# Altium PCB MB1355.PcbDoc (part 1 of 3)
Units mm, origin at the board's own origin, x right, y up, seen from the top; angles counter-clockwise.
Board outline 70.13 x 64.58 mm, 4 copper layers (L1, L2, L3, L4), stack 1.565 mm thick; 206 components, 160 nets, 707 pads, 1364 vias.
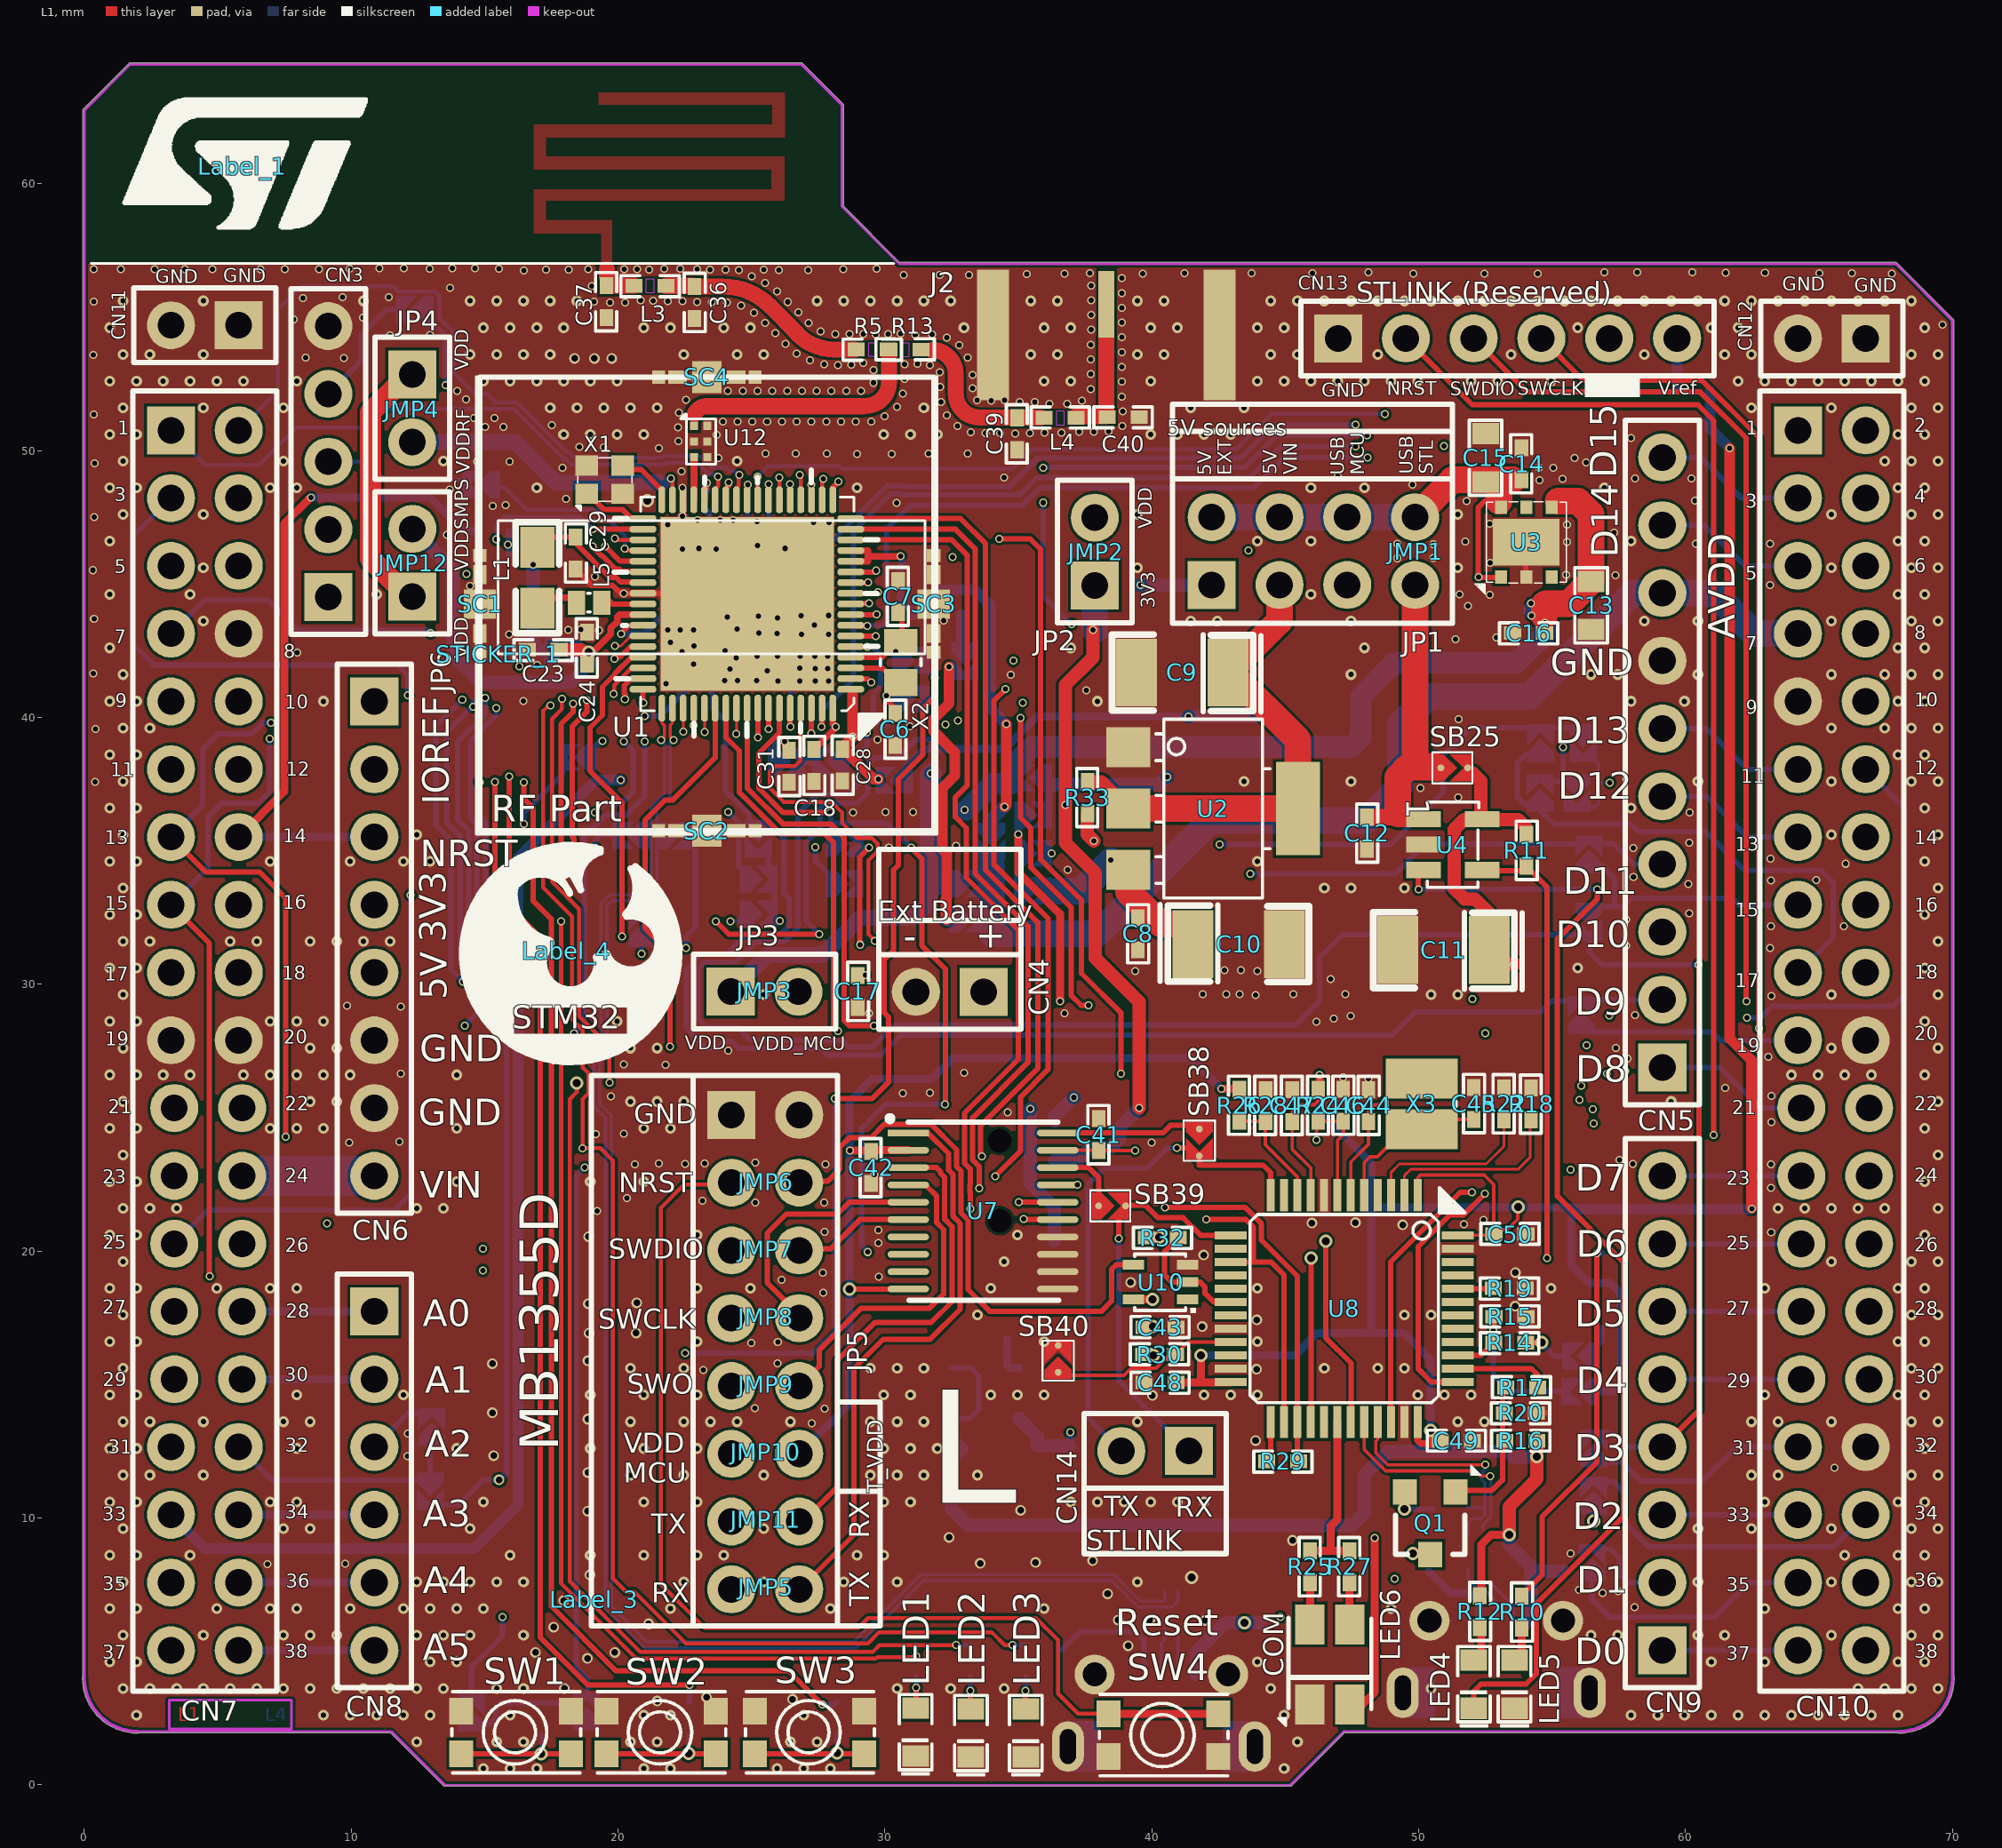
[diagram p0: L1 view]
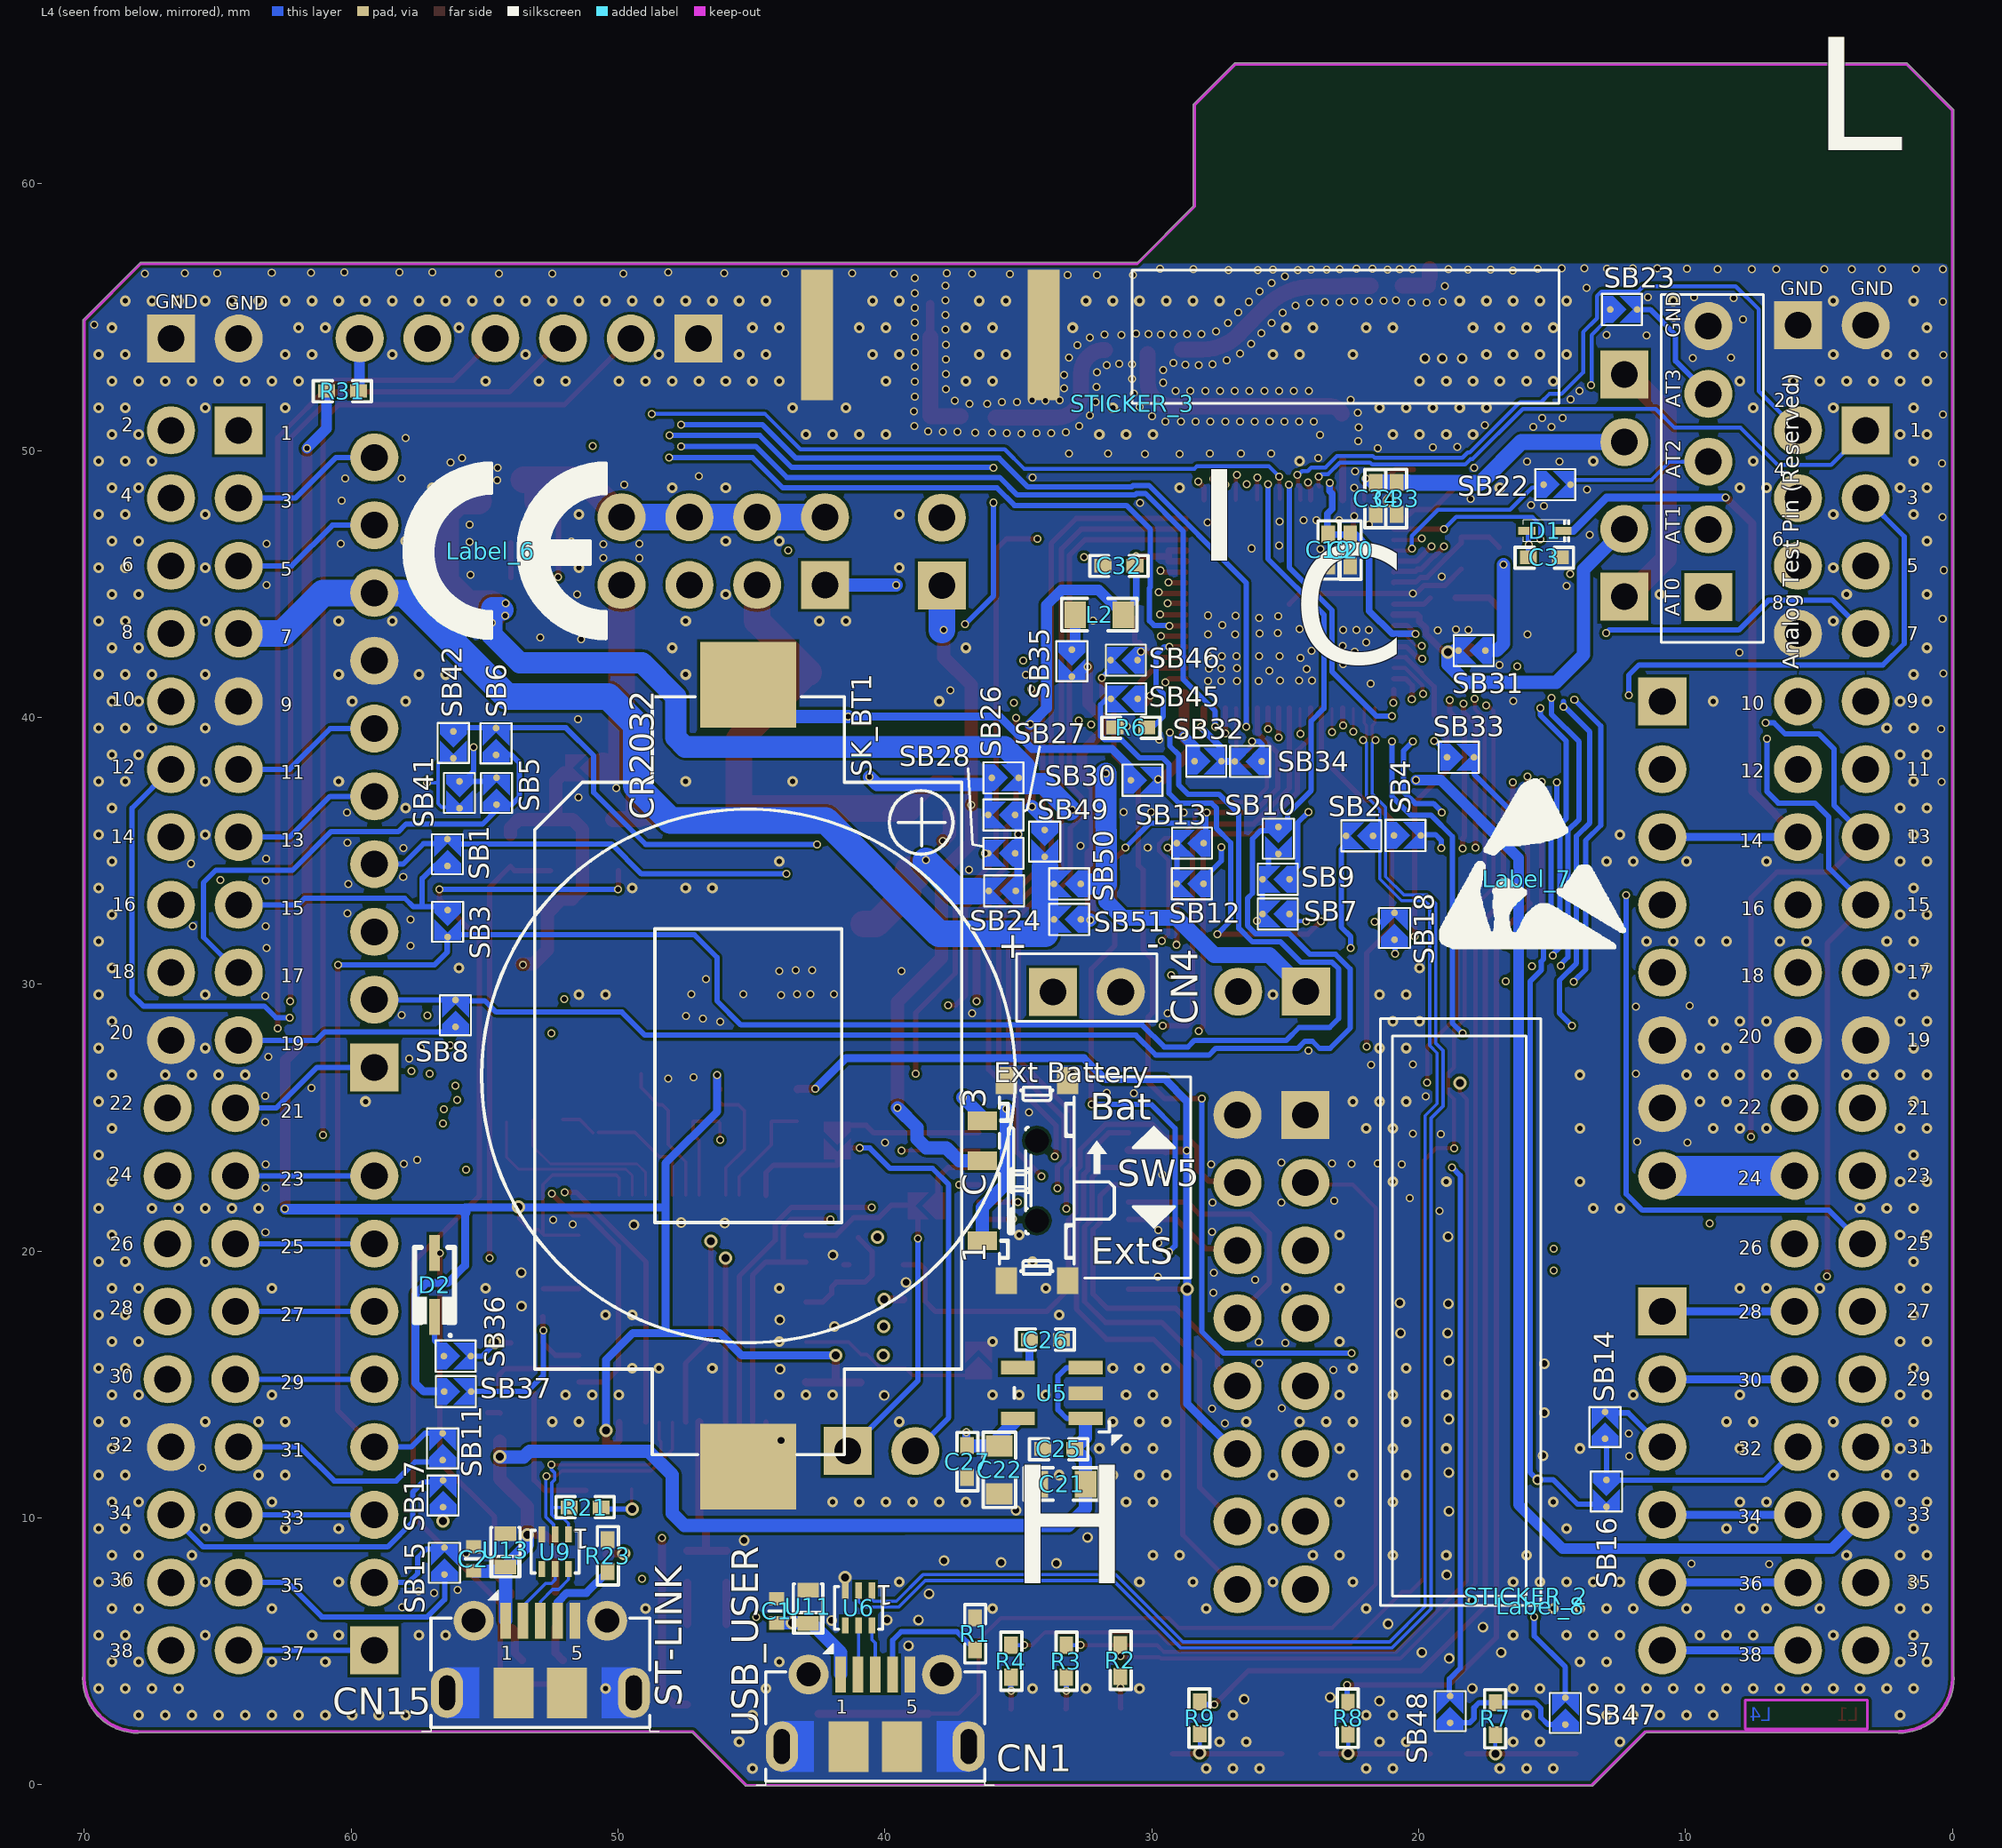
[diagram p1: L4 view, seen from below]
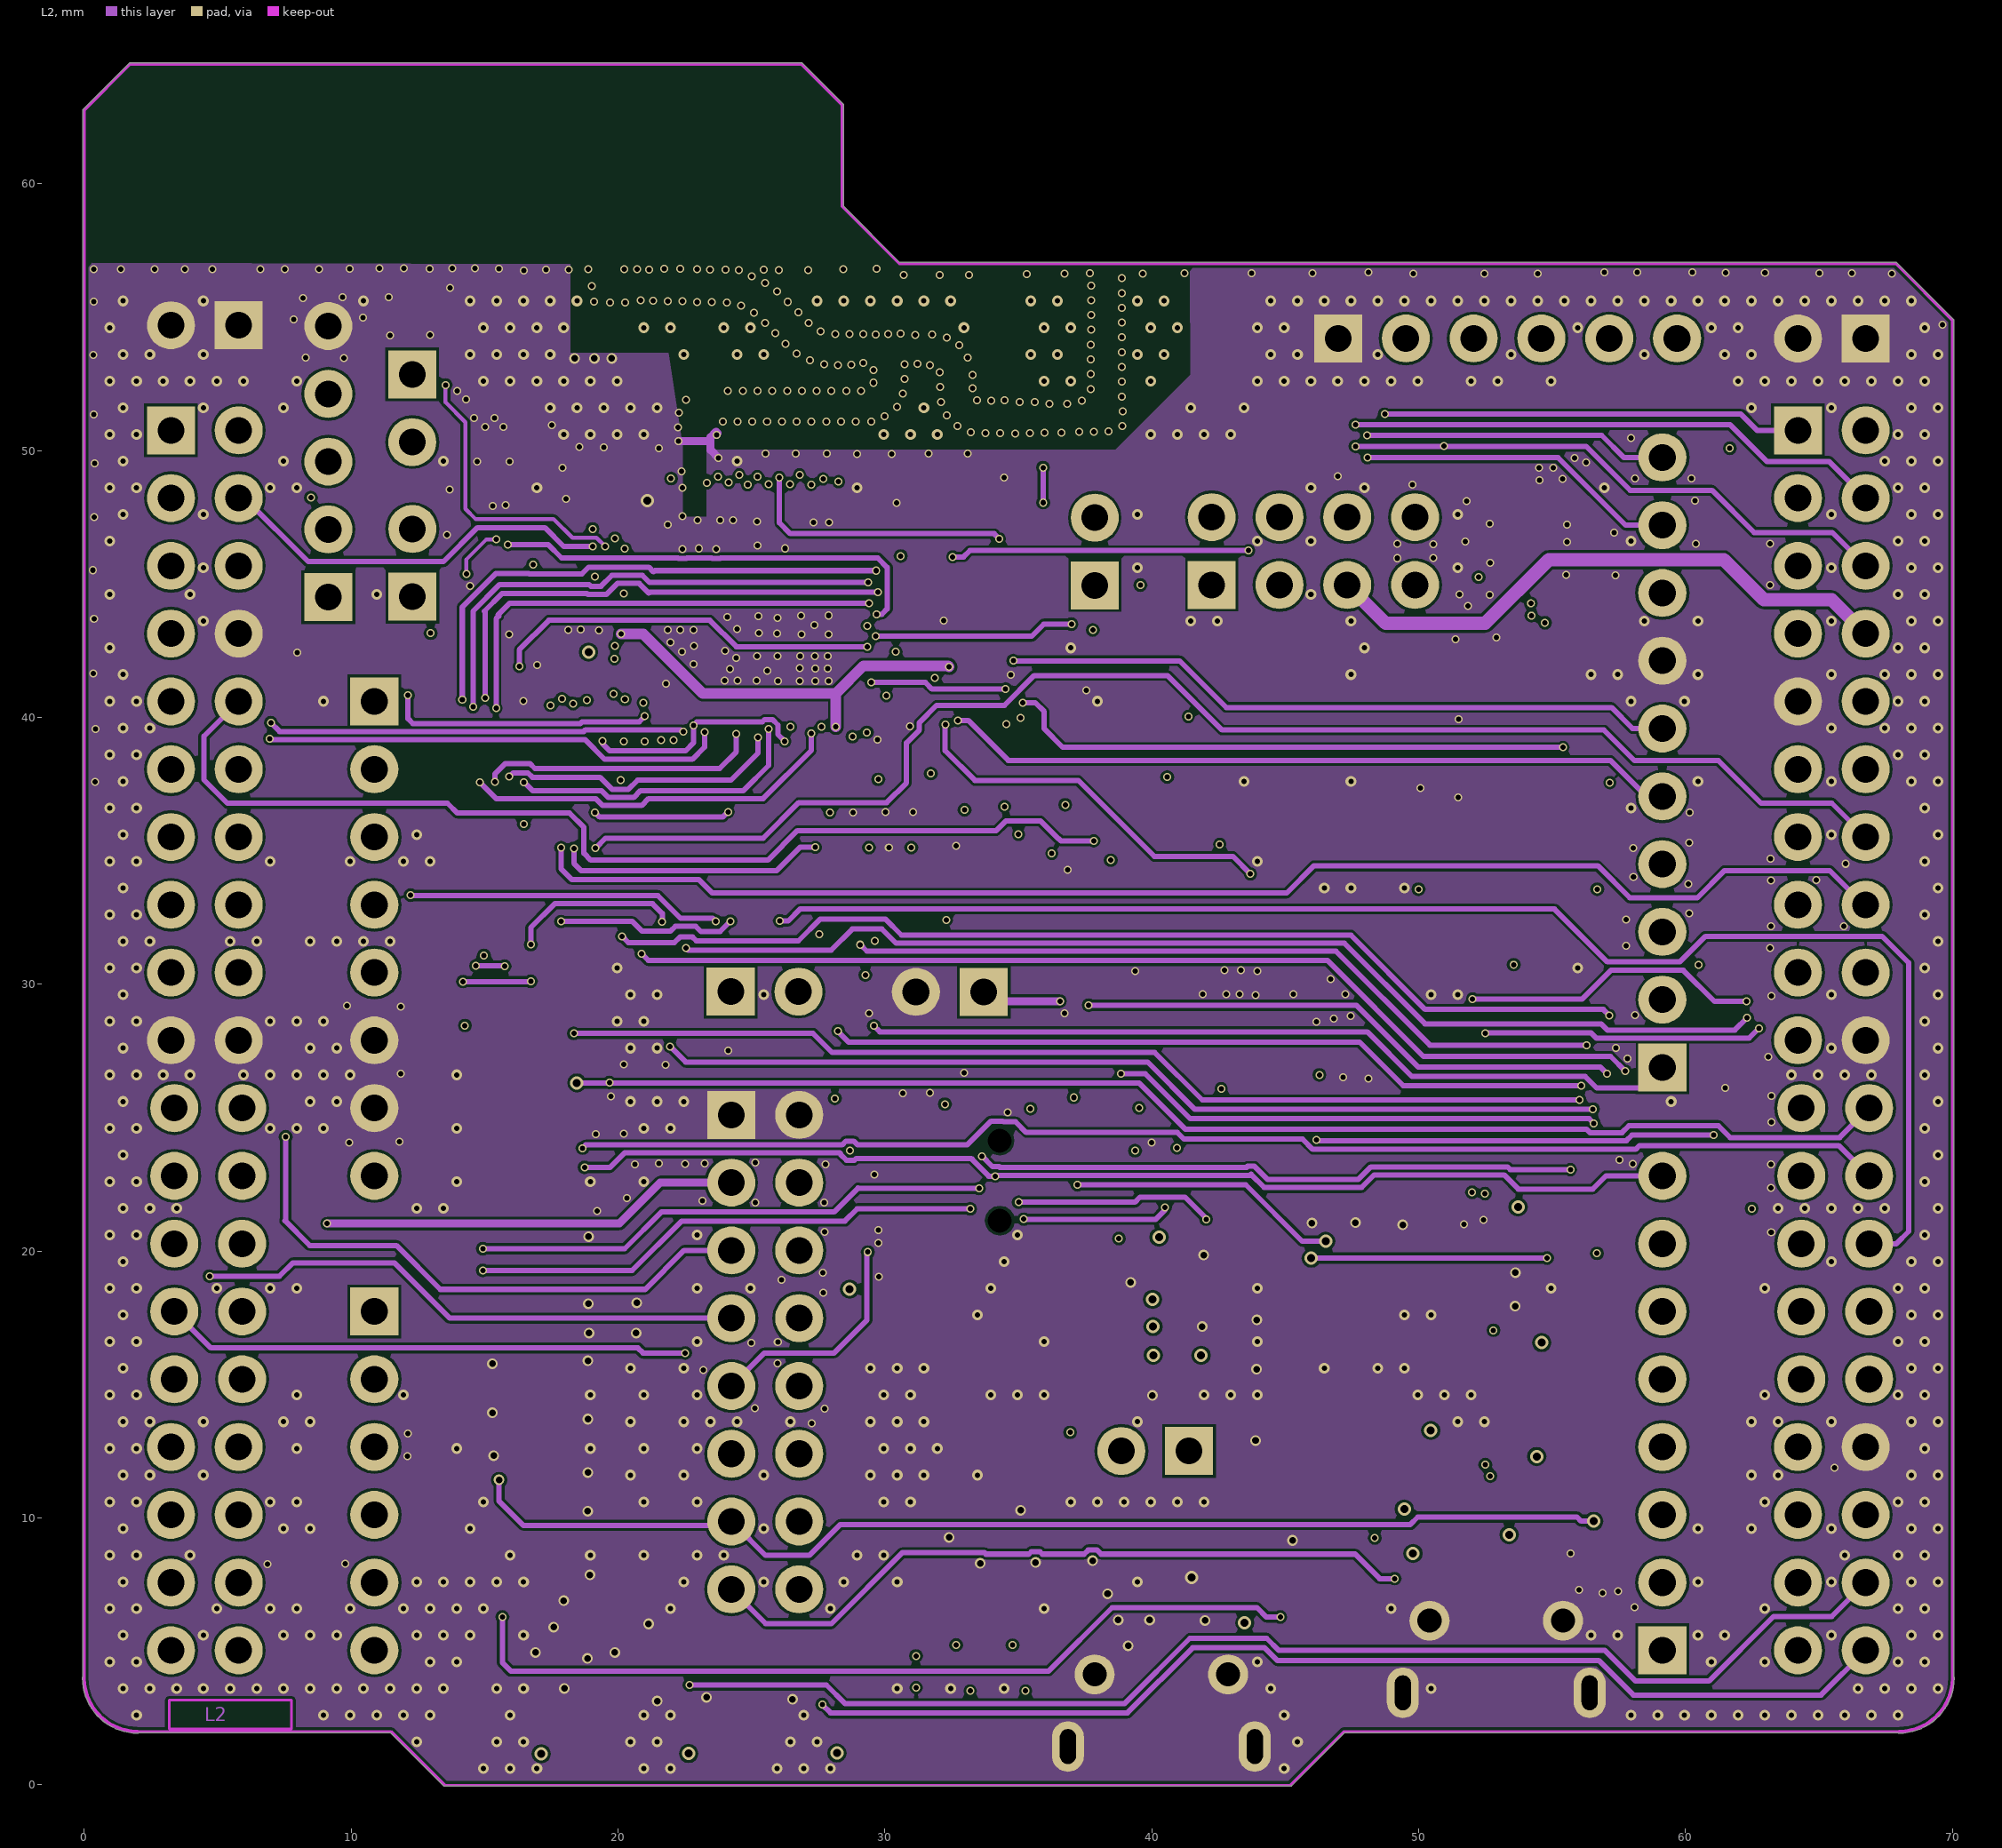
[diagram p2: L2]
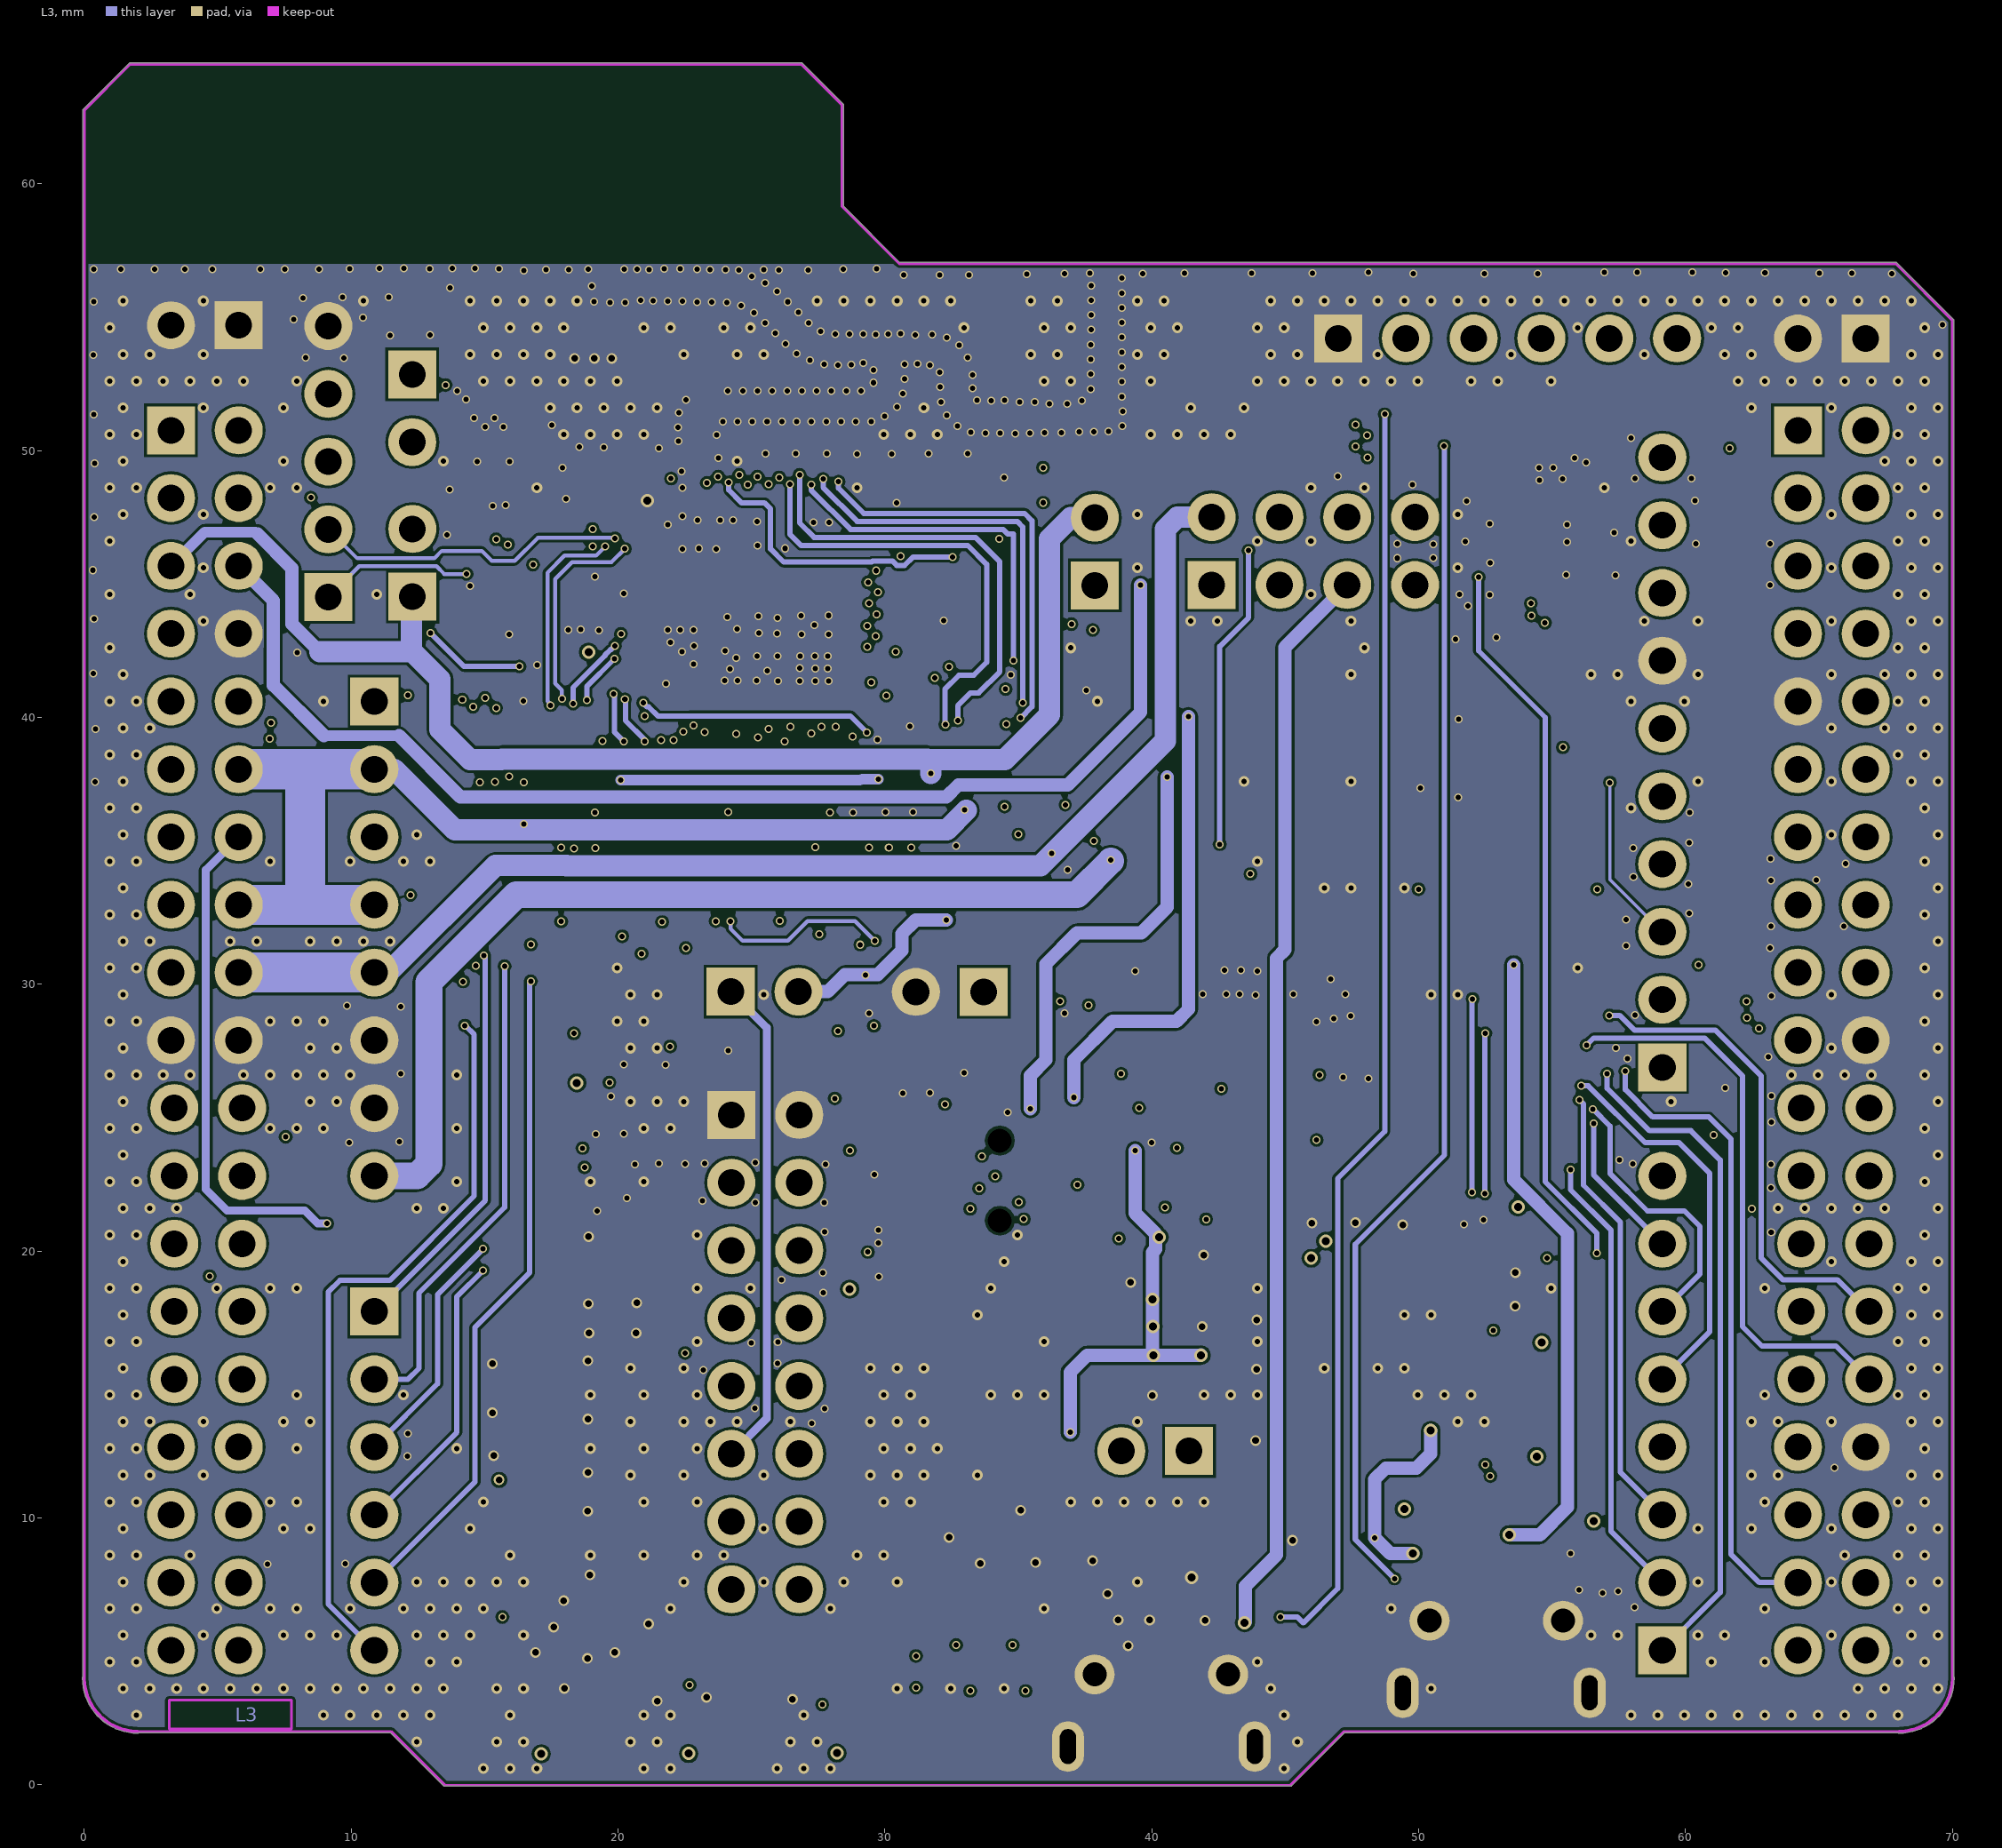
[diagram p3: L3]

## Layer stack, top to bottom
Top Solder: solder mask 0.0178, Solder Resist, Dk 4
L1: signal copper 0.0406
Dielectric1: core 0.4572, FR-4, Dk 4.2
L2: signal copper 0.0305
Dielectric 3: prepreg 0.508, Dk 4.4
L3: signal copper 0.0305
Dielectric 2: core 0.4572, FR-4, Dk 4.2
L4: signal copper 0.0406
Bottom Solder: solder mask 0.0178, Solder Resist, Dk 4

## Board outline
2,1.936 ccw(c2,2) 2.039,1.95 11.479,1.95 13.464,-0.036 13.464,-0.035 ccw(c13.5,0) 13.5,-0.05 45.2,-0.05 ccw(c45.2,0) 45.236,-0.035 45.236,-0.036 47.221,1.95 67.961,1.95 ccw(c68,2) 68,1.936 ccw(c68,4) 70.064,4 ccw(c70,4) 70.05,4.039 70.05,54.876 ccw(c70,54.876) 70.035,54.912 70.036,54.912 67.912,57.036 67.912,57.035 ccw(c67.876,57) 67.876,57.05 30.559,57.05 28.446,59.163 28.446,62.952 ccw(c28.396,62.952) 28.431,62.988 28.432,62.988 26.908,64.512 26.908,64.511 ccw(c26.872,64.476) 26.872,64.526 1.726,64.526 ccw(c1.726,64.476) 1.69,64.511 1.69,64.512 -0.036,62.786 -0.035,62.786 ccw(c0,62.75) -0.05,62.75 -0.05,4.039 ccw(c0,4) -0.064,4 ccw(c2,4)

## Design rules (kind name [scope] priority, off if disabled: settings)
AssemblyTestPointUsage [All] p1 off:
AssemblyTestpoint [All] p1 off: testpointundercomponent=TRUE minsize=1.016 maxsize=2.54 preferedsize=1.524 minholesize=0 maxholesize=1.016 preferedholesize=0.813 testpointgrid=0.025 usegrid=TRUE gridtolerance=0 allowsidetop=TRUE allowsidebottom=TRUE
Clearance "50ohms Net_R5_1" [InNet('NetR5_1')] p1: gap=0.126 ignorepadtopadclearanceinfootprint=FALSE
Clearance "Pads IPD A3" [Ispad and InNet('NetU1_31')] p2: gap=0.1 ignorepadtopadclearanceinfootprint=FALSE except(0.15: SMDPad-Poly)
Clearance "Pads IPD A1" [Ispad and InNet('NetR5_1')] p3: gap=0.1 ignorepadtopadclearanceinfootprint=FALSE except(0.15: SMDPad-Poly)
Clearance Clearance_2 [All] p4: gap=0.1 ignorepadtopadclearanceinfootprint=FALSE
ComponentClearance [All] p1 off: gap=0.254 collisioncheckmode=3 verticalgap=0.254 showdistances=FALSE
DiffPairsRouting [All] p1: maxlimit=0.1 minlimit=0.1 mostfreqgap=0.1 toplayer_minwidth=0.12 toplayer_maxwidth=0.12 toplayer_prefwidth=0.12 midlayer1_minwidth=0.12 midlayer1_maxwidth=0.12 midlayer1_prefwidth=0.12 midlayer4_minwidth=0.12 midlayer4_maxwidth=0.12 midlayer4_prefwidth=0.12 bottomlayer_minwidth=0.12 bottomlayer_maxwidth=0.12 bottomlayer_prefwidth=0.12 maxuncoupledlength=12.7
FabricationTestPointUsage TestPointUsage [All] p1 off: valid=0 allowmultiple=FALSE
FabricationTestpoint Testpoint [(IsPad And (OnTopLayer Or OnBottomLayer))] p1 off: side=3 testpointundercomponent=TRUE minsize=1.016 maxsize=2.54 preferedsize=1.524 minholesize=0 maxholesize=1.016 preferedholesize=0.813 testpointgrid=0.025 allowsidetop=TRUE allowsidebottom=TRUE usegrid=TRUE gridtolerance=0
FanoutControl Fanout_BGA [IsBGA] p1 off: bgadir=Out bgaviamode=Centered fanoutstyle=Auto fanoutdirection=Alternating viagrid=0.025 // Fanout_BGA (Default Rule)
FanoutControl Fanout_LCC [IsLCC] p2 off: bgadir=Out bgaviamode=Centered fanoutstyle=Auto fanoutdirection=Alternating viagrid=0.025 // Fanout_LCC (Default Rule)
FanoutControl Fanout_SOIC [IsSOIC] p3 off: bgadir=Out bgaviamode=Centered fanoutstyle=Auto fanoutdirection=Alternating viagrid=0.025 // Fanout_SOIC (Default Rule)
FanoutControl Fanout_Small [(CompPinCount < 5)] p4 off: bgadir=Out bgaviamode=Centered fanoutstyle=Auto fanoutdirection=OutThenIn viagrid=0.025 // Fanout_Small (Default Rule)
FanoutControl Fanout_Default [All] p5 off: bgadir=Out bgaviamode=Centered fanoutstyle=Auto fanoutdirection=Alternating viagrid=0.025 // Fanout_Default (Default Rule)
Height [All] p1 off: minheight=0 maxheight=25.4 prefheight=12.7
HoleSize [All] p1: absolutevalues=TRUE maxlimit=3.81 minlimit=0.2 maxpercent=80.000 minpercent=20.000
HoleToHoleClearance [All] p1 off: gap=0.254 allowstackedmicrovias=TRUE
LayerPairs [All] p1 off: enforce=FALSE
MinimumAnnularRing [All] p1 off: minimumring=0.102
MinimumSolderMaskSliver [All] p1 off: minsoldermaskwidth=0.254
NetAntennae [All] p1 off: netantennaetolerance=0
PlaneClearance [All] p1 off: clearance=0.508
PlaneConnect [All] p1: planeconnectstyle=Direct reliefexpansion=0.508 reliefentries=4 reliefconductorwidth=0.254 reliefairgap=0.254
PolygonConnect [All] p1: connectstyle=Direct reliefconductorwidth=0.508 reliefentries=4 polygonreliefangle="90 Angle" airgapwidth=0.254
RoutingCorners [All] p1 off: cornerstyle=45-Degree minsetback=2.54 maxsetback=2.54
RoutingLayers [All] p1 off: top layer_v5=TRUE mid layer 1_v5=TRUE mid layer 4_v5=TRUE bottom layer_v5=TRUE
RoutingPriority [All] p1 off: routingpriority=0
RoutingTopology [All] p1 off: topology=Shortest
RoutingVias [All] p1: holewidth=0.3 width=0.4 viastyle="Through Hole" minholewidth=0.1 minwidth=0.2 maxholewidth=3.6 maxwidth=6
SilkToBoardRegionClearance [All] p1 off:
SilkToSilkClearance [All] p1 off: silktosilkclearance=0.254
SilkToSolderMaskClearance SilkscreenOverComponentPads [IsPad] p1 off: minsilkscreentomaskgap=0.254 clearancetoexposedcopper=TRUE
SolderMaskExpansion [All] p1: expansion=0.102
Width [All] p1: maxlimit=6 minlimit=0.075 preferedwidth=0.2 midlayer4_minwidth=0.1 bottomlayer_minwidth=0.1 minimp=50.000000 maximp=50.000000 favimp=50.000000
4 further rules are at their usual default settings.

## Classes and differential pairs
component class MCU: C3 C6 C7 CN3 D1 LED1 LED2 LED3 R2 R3 R4 R6 R7 R8 R9 SB22 SB23 SB45 SB46 SB47 SB48 SW1 SW2 SW3 SW4 X1 X2
net class DIFF90: USB_N USB_P USBSTLK_N USBSTLK_P
component class ST_LINK_V2-1: C2 C41 C42 C43 C44 C45 C46 C47 C48 C49 C50 CN13 CN14 CN15 D2 JMP5 JMP6 JMP7 JMP8 JMP9 JMP10 JMP11 JP5 LD1 LED6 Q1 R14 R15 R16 R17 R18 R19 R20 R21 R22 R23 R24 R25 R26 R27 R28 R29 R30 R31 R32 SB36 SB37 SB38 SB39 SB40 U7 U8 U9 U10 U13 X3
component class RF: C33 C34 C36 C37 C39 C40 J2 J? JMP4 JP4 L3 L4 R5 R13 SC1 SC2 SC3 SC4 SH1 U1 U12
component class Power_managment: C8 C9 C10 C11 C12 C13 C14 C15 C16 C17 C18 C19 C20 C21 C22 C23 C24 C25 C26 C27 C28 C29 C31 C32 CN4 CN11 CN12 JMP1 JMP2 JMP3 JMP12 JP1 JP2 JP3 JP6 L1 L2 L5 LD3 LED4 LED5 R10 R11 R12 SB24 SB25 SB26 SB27 SB28 SB30 SB31 SB32 SB33 SB34 SB35 SB49 SB50 SB51 SK_BT1 SW5 T2 U2 U3 U4 U5
component class Extension_CN: C1 CN1 CN5 CN6 CN7 CN8 CN9 CN10 R1 R33 SB1 SB2 SB3 SB4 SB5 SB6 SB7 SB8 SB9 SB10 SB11 SB12 SB13 SB14 SB15 SB16 SB17 SB18 SB41 SB42 U6 U11
component class Project_Overview: Label_1 Label_3 Label_4 Label_5 Label_6 Label_7 Label_8 Label_9 STICKER_1 STICKER_2 STICKER_3
differential pair USB: +USB_P -USB_N
differential pair USBSTLK: +USBSTLK_P -USBSTLK_N

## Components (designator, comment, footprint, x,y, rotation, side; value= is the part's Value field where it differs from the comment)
C1 "Capacitor" C0402 44.054,6.52 r270 bottom value=100pF
C2 "Capacitor" C0402 55.412,8.469 r90 bottom value=100pF
C3 "100nF" 0402_CAP_NPOL 15.294,45.998 r0 bottom
C6 "10pF" 0402_CAP_NPOL 30.387,39.556 r270 top
C7 "10pF" 0402_CAP_NPOL 30.496,44.535 r90 top
C8 "100nF/25V" 0402_CAP_NPOL 39.48,31.894 r270 top
C9 "10uF/25V" 1210_CAP_POL 41.142,41.684 r180 top
C10 "10uF/25V" 1210_CAP_POL 43.26,31.504 r0 top
C11 "4.7uF/10V" 1210_CAP_POL 50.93,31.284 r180 top
C12 "100nF" 0402_CAP_NPOL 48.057,35.664 r270 top
C13 "1uF/X5R" 0603_CAP_NPOL 56.46,44.198 r270 top
C14 "100nF" 0402_CAP_NPOL 53.852,49.505 r90 top
C15 "1uF/X5R" 0603_CAP_NPOL 52.507,49.731 r90 top
C16 "100nF" 0402_CAP_NPOL 54.119,43.161 r180 top
C17 "100nF" 0402_CAP_NPOL 28.985,29.732 r270 top
C18 "100nF" 0402_CAP_NPOL 27.344,38.203 r270 top
C19 "100nF" 0402_CAP_NPOL 23.392,46.276 r270 bottom
C20 "100nF" 0402_CAP_NPOL 22.564,46.272 r270 bottom
C21 "1uF/X5R" 0603_CAP_NPOL 33.38,11.274 r0 bottom
C22 "1uF/X5R" 0603_CAP_NPOL 35.71,11.804 r270 bottom
C23 "4.7uF" 0402_CAP_NPOL 17.196,42.535 r180 top
C24 "100nF" 0402_CAP_NPOL 18.845,42.603 r90 top
C25 "100nF" 0402_CAP_NPOL 33.49,12.594 r0 bottom
C26 "100nF" 0402_CAP_NPOL 33.99,16.674 r180 bottom
C27 "100nF" 0402_CAP_NPOL 36.92,12.114 r270 bottom
C28 "100nF" 0402_CAP_NPOL 28.41,38.212 r270 top
C29 "4.7uF" 0402_CAP_NPOL 18.408,46.159 r270 top
C31 "100nF" 0402_CAP_NPOL 26.409,38.163 r270 top
C32 "100nF" 0402_CAP_NPOL 31.23,45.689 r0 bottom
C33 "100nF" 0402_CAP_NPOL 20.828,48.205 r90 bottom
C34 "100pF" 0402_CAP_NPOL 21.611,48.2 r90 bottom
C36 "" 0402_CAP_NPOL 22.863,55.551 r270 top
C37 "1.2pF" 0402_CAP_NPOL 19.566,55.578 r90 top
C39 "" 0402_CAP_NPOL 34.957,50.63 r90 top
C40 "" 0402_CAP_NPOL 38.924,51.256 r180 top
C41 "100nF" 0402_CAP_NPOL 38.011,24.365 r90 top
C42 "100nF" 0402_CAP_NPOL 29.478,23.131 r90 top
C43 "100nF" 0402_CAP_NPOL 40.31,17.146 r0 top
C44 "20pF" 0402_CAP_NPOL 48.12,25.456 r270 top
C45 "20pF" 0402_CAP_NPOL 52.064,25.532 r270 top
C46 "100nF" 0402_CAP_NPOL 47.17,25.466 r270 top
C47 "100nF" 0402_CAP_NPOL 45.26,25.456 r90 top
C48 "100nF" 0402_CAP_NPOL 40.31,15.076 r180 top
C49 "100nF" 0402_CAP_NPOL 51.414,12.886 r0 top
C50 "100nF" 0402_CAP_NPOL 53.42,20.636 r0 top
CN1 "1050170001" USBMICROB_MOLEX_105017-0001_H2P90 40.359,-0.015 r180 bottom
CN3 "HEADER_1X5" "Header NF 1x5x2.54 TH" 9.146,44.507 r90 top
CN4 "HEADER_1X2" "Header NF 1x2x2.54 TH" 33.703,29.714 r180 top
CN5 "HEADER_1X10" "Header F 1x10x2.54 TH V" 59.13,26.884 r90 top locked
CN6 "HEADER_1X8_F" "Header F 1x8x2.54 TH V" 10.87,40.6 r270 top locked
CN7 "HEADER_2X19_M" "Header M 2x19x2.54 TH M_top + M_bottom" 3.25,50.76 r270 top locked
CN8 "HEADER_1X6" "Header F 1x6x2.54 TH V" 10.87,17.74 r270 top locked
CN9 "HEADER_1X8_F" "Header F 1x8x2.54 TH V" 59.13,5.04 r90 top locked
CN10 "HEADER_2X19_M" "Header M 2x19x2.54 TH M_top + M_bottom" 64.21,50.76 r270 top locked
CN11 "HEADER_1X2" "Header M 1x2x2.54 TH V" 5.79,54.697 r180 top
CN12 "HEADER_1X2" "Header M 1x2x2.54 TH V" 66.75,54.2 r180 top
CN13 "HEADER_1X6" "Header NF 1x6x2.54 TH" 46.98,54.204 r0 top
CN14 "HEADER_1X2" "Header NF 1x2x2.54 TH" 41.398,12.509 r180 top
CN15 "1050170001" USBMICROB_MOLEX_105017-0001_H2P90 52.907,2 r180 bottom
D1 "BAT54KFILM" SOD523 15.27,46.998 r180 bottom
D2 "BAT60JFILM" SOD-323 56.87,18.734 r270 bottom
J2 "SMA" SMA_T_9.52_NF 38.298,57.894 r90 top
JMP1 "Jumper 2.54mm" "Jumper 2.54mm BLACK" 49.871,46.225 r270 top
JMP2 "Jumper 2.54mm" "Jumper 2.54mm BLACK" 37.897,46.196 r90 top
JMP3 "Jumper 2.54mm" "Jumper 2.54mm BLACK" 25.482,29.761 r0 top
JMP4 "Jumper 2.54mm" "Jumper 2.54mm BLACK" 12.269,51.546 r270 top
JMP5 "Jumper 2.54mm" "Jumper 2.54mm BLACK" 25.538,7.412 r180 top
JMP6 "Jumper 2.54mm" "Jumper 2.54mm BLACK" 25.538,22.599 r180 top
JMP7 "Jumper 2.54mm" "Jumper 2.54mm BLACK" 25.538,20.068 r180 top
JMP8 "Jumper 2.54mm" "Jumper 2.54mm BLACK" 25.538,17.537 r180 top
JMP9 "Jumper 2.54mm" "Jumper 2.54mm BLACK" 25.538,15.005 r180 top
JMP10 "Jumper 2.54mm" "Jumper 2.54mm BLACK" 25.538,12.474 r180 top
JMP11 "Jumper 2.54mm" "Jumper 2.54mm BLACK" 25.538,9.943 r180 top
JMP12 "Jumper 2.54mm" "Jumper 2.54mm BLACK" 12.339,45.779 r90 top
JP1 "HEADER_2X4" "Header M 2x4x2.54 TH V" 42.245,44.965 r0 top
JP2 "HEADER_1X2" "Header M 1x2x2.54 TH V" 37.867,44.946 r90 top
JP3 "HEADER_1X2" "Header M 1x2x2.54 TH V" 24.222,29.723 r0 top
JP4 "HEADER_1X2" "Header M 1x2x2.54 TH V" 12.289,52.856 r270 top
JP5 "HEADER_2X8" "Header M 2x8x2.54 TH V" 24.247,25.107 r270 top
JP6 "HEADER_1X2" "Header M 1x2x2.54 TH V" 12.296,44.523 r90 top
L1 "10uH" 0805_COIL 16.98,46.377 r270 top
L2 "FCM1608KF-601T03" 0603_COIL 31.965,43.852 r180 bottom
L3 "3.6nH" 0402_COIL 21.201,56.173 r180 top
L4 "0R" 0402_COIL 36.571,51.226 r0 top
L5 "Inductor" IND_0402_MURATA_LQW15AN_H0P5 18.912,44.302 r0 top value=10nH
Label_1 "LOGO_ST" LOGO_ST_Size3 5.925,60.67 r0 top
Label_3 "LOGO_Nucleo_www" LOGO_Nucleo_www 19.111,6.957 r90 top
Label_4 "LOGO_STM32" LOGO_STM32 18.074,31.267 r0 top
Label_6 "LOGO_CE" "LOGO CE" 54.761,46.246 r180 bottom
Label_7 "LOGO_ESD" "LOGO ESD" 15.952,33.972 r180 bottom
Label_8 "LOGO_StickerArea_W21x6" LOGO_StickerArea_Border 15.425,6.72 r90 bottom
LED1 "LED BLUE" 0603_LED_Blue 31.15,1.974 r90 top
LED2 "LED GREEN" 0603_LED_GREEN 33.22,1.944 r90 top
LED3 "LED RED" 0603_LED_RED 35.28,1.944 r90 top
LED4 "LED RED" 0603_LED_RED 52.069,3.77 r90 top
LED5 "LED RED" 0603_LED_RED 53.593,3.77 r90 top
LED6 "HSMF-A201-A00J1/KAA-3528SURKCGKC" HSMF-A201 46.67,4.514 r90 top
Q1 "2N2222" SOT23-3 50.432,8.629 r180 top
R1 "100K" 0402_RES 36.627,5.66 r270 bottom
R2 "680" 0402_RES 31.175,4.664 r270 bottom
R3 "680" 0402_RES 33.205,4.634 r270 bottom
R4 "680" 0402_RES 35.275,4.634 r270 bottom
R5 "0R" 0402_RES 29.526,53.795 r180 top
R6 "10K" 0402_RES 30.781,39.629 r0 bottom
R7 "1K" 0402_RES 17.124,2.478 r90 bottom
R8 "1K" 0402_RES 22.646,2.496 r90 bottom
R9 "1K" 0402_RES 28.203,2.504 r90 bottom
R10 "1K" 0402_RES 53.863,6.476 r270 top
R11 "10K" 0402_RES 54.034,35.021 r270 top
R12 "1K" 0402_RES 52.29,6.495 r270 top
R13 "nc" 0402_RES 30.759,53.784 r0 top
R14 "2K7" 0402_RES 53.41,16.566 r180 top
R15 "4K7" 0402_RES 53.42,17.546 r0 top
R16 "10K" 0402_RES 53.826,12.886 r0 top
R17 "100" 0402_RES 53.856,14.889 r0 top
R18 "10K" 0402_RES 54.214,25.512 r90 top
R19 "100K" 0402_RES 53.4,18.606 r180 top
R20 "36K" 0402_RES 53.816,13.933 r180 top
R21 "1K5" 0402_RES 51.232,10.389 r180 bottom
R22 "10K" 0402_RES 53.194,25.522 r90 top
R23 "100K" 0402_RES 50.39,8.584 r270 bottom
R24 "100K" 0402_RES 46.24,25.466 r90 top
R25 "100/2K7" 0402_RES 45.93,8.174 r90 top
R26 "4K7" 0402_RES 43.28,25.466 r90 top
R27 "100/100" 0402_RES 47.41,8.174 r90 top
R28 "4K7" 0402_RES 44.26,25.456 r90 top
R29 "100" 0402_RES 44.91,12.126 r180 top
R30 "" 0402_RES 40.29,16.126 r0 top
R31 "10" 0402_RES 60.326,52.233 r0 bottom
R32 "100K" 0402_RES 40.4,20.506 r180 top
R33 "1K" 0402_RES 37.593,36.995 r90 top
SB1 "Close" SB-tiny 56.39,34.934 r90 bottom
SB2 "Open" SB-tiny 22.21,35.562 r0 bottom
SB3 "Open" SB-tiny 56.381,32.281 r270 bottom
SB4 "Open" SB-tiny 20.427,35.575 r180 bottom
SB5 "Close" SB-tiny 54.55,37.234 r90 bottom
SB6 "Open" SB-tiny 54.57,39.094 r90 bottom
SB7 "Open" SB-tiny 25.34,32.633 r0 bottom
SB8 "Close" SB-tiny 56.09,28.904 r90 bottom
SB9 "Close" SB-tiny 25.34,33.937 r0 bottom
SB10 "Open" SB-tiny 25.256,35.395 r270 bottom
SB11 "Close" SB-tiny 56.571,12.669 r90 bottom
SB12 "Close" SB-tiny 28.561,33.767 r0 bottom
SB13 "Open" SB-tiny 28.558,35.288 r0 bottom
SB14 "Close" SB-tiny 13.016,13.469 r90 bottom
SB15 "Close" SB-tiny 56.504,8.384 r90 bottom
SB16 "Open" SB-tiny 12.962,10.926 r270 bottom
SB17 "Close" SB-tiny 56.556,10.905 r90 bottom
SB18 "Open" SB-tiny 20.905,32.171 r90 bottom
SB22 "Open" SB-tiny 14.819,48.724 r180 bottom
SB23 "Open" SB-tiny 12.321,55.287 r180 bottom
SB24 "Open" SB-tiny 35.597,33.5 r0 bottom
SB25 "Open" SB-tiny 51.331,38.11 r0 top
SB26 "Close" SB-tiny 35.493,37.737 r180 bottom
SB27 "Open" SB-tiny 35.622,36.348 r0 bottom
SB28 "Open" SB-tiny 35.619,34.908 r0 bottom
SB30 "Open" SB-tiny 30.284,37.648 r180 bottom
SB31 "Open" SB-tiny 18.002,42.506 r0 bottom
SB32 "Close" SB-tiny 27.896,38.358 r180 bottom
SB33 "Close" SB-tiny 18.435,38.505 r180 bottom
SB34 "Open" SB-tiny 26.384,38.352 r0 bottom
SB35 "Close" SB-tiny 32.994,42.039 r270 bottom
SB36 "Close" SB-tiny 56.023,16.067 r180 bottom
SB37 "Open" SB-tiny 56.011,14.739 r180 bottom
SB38 "Close" SB-tiny 41.78,24.076 r270 top
SB39 "Close" SB-tiny 38.51,21.696 r0 top
SB40 "Open" SB-tiny 36.493,15.96 r90 top
SB41 "Close" SB-tiny 55.94,37.104 r270 bottom
SB42 "Open" SB-tiny 56.17,38.976 r270 bottom
SB45 "Open" SB-tiny 31.025,40.698 r0 bottom
SB46 "Open" SB-tiny 31.035,42.147 r0 bottom
SB47 "Close" SB-tiny 14.505,2.759 r90 bottom
SB48 "Open" SB-tiny 18.821,2.823 r90 bottom
SB49 "Open" SB-tiny 34.014,35.285 r270 bottom
SB50 "Close" SB-tiny 33.16,33.761 r0 bottom
SB51 "Open" SB-tiny 33.156,32.429 r0 bottom
SC1 "Shield Clip_A 3.9x1.1x1.28" "Shield Clip_A 3.9x1.1x1.28" 14.829,44.252 r90 top locked
SC2 "Shield Clip_A 3.9x1.1x1.28" "Shield Clip_A 3.9x1.1x1.28" 23.329,35.752 r180 top
SC3 "Shield Clip_A 3.9x1.1x1.28" "Shield Clip_A 3.9x1.1x1.28" 31.829,44.252 r90 top
SC4 "Shield Clip_A 3.9x1.1x1.28" "Shield Clip_A 3.9x1.1x1.28" 23.329,52.752 r180 top locked
SH1 "Shield 17.2x17.2x3" "Shield 17.2x17.2x3" -3.118,7.015 r0 top
SK_BT1 "CR2032-SCK1B" CR2032-SCK1 45.12,26.574 r90 bottom locked
STICKER_1 "FCC_ID_Sticker_16x5" "Sticker_FCC_ID 16x5mm" 15.505,42.373 r0 top
STICKER_2 "Sticker_BrdRef_21x5" Sticker_BrdRef_21x5mm 15.978,7.065 r90 bottom
STICKER_3 "Sticker_CPN_FG 16x5" "Sticker_CPN_FG 16x5mm" 30.737,51.764 r180 bottom
SW1 "User PB" "SW-PB SMD KMR2" 16.18,1.967 r0 top
SW2 "User PB" "SW-PB SMD KMR2" 21.614,1.967 r0 top
SW3 "User PB" "SW-PB SMD KMR2" 27.177,1.967 r0 top
SW4 "Reset PB" "SW-PB SMD KMR2" 40.436,1.865 r0 top
SW5 "SW_MECA_1K2" SWI_SPDT-RA_TE-CONNECTIVITY_MLL1200S_1P2T 34.305,22.641 r90 bottom value=MLL1200S
U1 "STM32WBxx_QFN68" VFQFPN68_8x8x0.1_p0.4 24.844,44.252 r180 top
U2 "LD1117S50TR" SOT223_SC73_A 42.3,36.584 r270 top
U3 "LD39050PU33R" "DFN6 3x3mm" 54.031,46.566 r0 top
U4 "TPS2041C" MOS_SOT23-5L 51.275,35.232 r270 top
U5 "LD3985M33R" SOT23-5 33.75,14.684 r0 bottom
U6 "ECMF02-2AMX6" ESD_QFN-6L_1P7X1P5_P050 40.986,6.63 r0 bottom
U7 "TXS0108EPW" TSSOP20 30.875,24.431 r0 top
U8 "STM32F103CBT6" LQFP48_7X7_P050 47.21,17.846 r180 top
U9 "ECMF02-2AMX6" ESD_QFN-6L_1P7X1P5_P050 52.352,8.736 r0 bottom
U10 "74LVC1G07" SOT353-1 41.27,18.186 r180 top
U11 "ESD-TRANSIL" ESD_QFN2_1P6X1_P125 42.875,6.68 r90 bottom value=ESDA7P60-1U1M
U12 "MLPF-WB55-01E3" ST_CSP650x58P2x3_160x100x42 23.095,50.342 r0 top
U13 "ESD-TRANSIL" ESD_QFN2_1P6X1_P125 54.22,8.791 r90 bottom value=ESDA7P60-1U1M
X1 "NX2016_32M" NX2016_4P 19.507,48.914 r0 top
X2 "NX2012_32K768" NX2012_2P 30.591,41.307 r90 top
X3 "XTAL_2_PINS" CRY_NX3225GD_2P 50.11,25.517 r90 top value="NX3225GD 8MHz"

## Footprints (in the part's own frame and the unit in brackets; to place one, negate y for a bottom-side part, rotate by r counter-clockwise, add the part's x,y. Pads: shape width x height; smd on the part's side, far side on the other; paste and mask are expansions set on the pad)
0402_CAP_NPOL [mil] "Capacitor FootPrint 0402"
  rect 25x20 smd: 1(-23.58,0) 2(23.58,0)
  silkscreen extent -43,-15 43,16, body extent -39,-14 41,14, height 32
0402_COIL [mil] "Coil FootPrint 0402"
  rect 25x20 smd: 1(-23.58,0) 2(23.58,0)
  silkscreen extent -43,-15 43,16, body extent -38,-11 39,13, height 16
0402_RES [mil] "Resistor FootPrint 0402"
  rect 25x20 smd: 1(-23.58,0) 2(23.58,0)
  silkscreen extent -43,-15 43,16, body extent -38,-11 39,13, height 16
0603_CAP_NPOL [mm] "Capacitor FootPrint 0603"
  rect 0.8x1 smd: 1(-0.902,0) 2(0.902,0)
  silkscreen extent -1.41,-0.61 1.41,0.61, body extent -1.28,-0.46 1.26,0.48, height 0.82
0603_COIL [mm] "Coil Footprint 0603"
  rect 0.8x1 smd: 1(-0.902,0) 2(0.902,0)
  silkscreen extent -1.41,-0.61 1.41,0.61, body extent -1.26,-0.48 1.26,0.48, height 0.4
0603_LED_Blue [mm] "Resistor Footprint 0603"
  rect 0.8x1 smd: A(0.902,0) K(-0.902,0)
  silkscreen extent -1.59,-0.61 1.41,0.61, body extent -1.26,-0.48 1.26,0.48, height 0.84
0603_LED_GREEN [mm] "Resistor Footprint 0603"
  rect 0.8x1 smd: A(0.902,0) K(-0.902,0)
  silkscreen extent -1.59,-0.61 1.41,0.61, body extent -1.26,-0.48 1.26,0.48, height 0.84
0603_LED_RED [mm] "Resistor Footprint 0603"
  rect 0.8x1 smd: A(0.902,0) K(-0.902,0)
  silkscreen extent -1.59,-0.61 1.41,0.61, body extent -1.26,-0.48 1.26,0.48, height 0.84
0805_COIL [mil] "Coil FootPrint 0805"
  rect 60x50 smd: 1(0,0) 2(90,0)
  silkscreen extent -37,-32 127,32, body extent -21,-25 113,25, height 16
1210_CAP_POL [mil] "Capacitor Polarized 1210"
  rect 60x100 smd: 1(-67.5,0) 2(67.5,0)
  silkscreen extent -116,-56 104,59, body extent -72,-57 73,58, height 80
C0402 [mm]
  rect 0.51x0.56 smd mask+0.05: 1(-0.45,0) 2(0.45,0)
  silkscreen extent 0,-0.3 0,0.3, body extent -0.5,-0.3 0.5,0.3, height 0.4
CR2032-SCK1 [mm]
  rect 3.2x3.6 smd: 1(14.65,0) 2(-14.65,0)
  silkscreen extent -14.2,-10.01 14.2,9.99, body extent -16.1,-8 16.1,8, height 5.6
CRY_NX3225GD_2P [mm]
  rect 1.5x2.7 smd mask+0.05: 1(-0.95,0) 2(0.95,0)
  silkscreen extent -0.1,-1.3 0.1,1.3, body extent -1.65,-1.3 1.65,1.3, height 1
"DFN6 3x3mm" [mm] "DFN6 3x3mm heigh=0.8mm"
  rect 0.45x0.5 smd mask+0.02: 1(-0.95,-1.3) 2(0,-1.3) 3(0.95,-1.3) 4(0.95,1.3) 5(0,1.3) 6(-0.95,1.3)
  rect 2.5x1.75 smd mask+0.02: 7(0,0)
  silkscreen extent -1.93,-1.94 1.5,1.52, body extent -1.52,-1.52 1.52,1.52, height 0.9
ESD_QFN2_1P6X1_P125 [mm]
  rect 0.55x0.8 smd mask+0.05: 1(-0.625,0) 2(0.625,0)
  silkscreen extent -1,-0.55 0.85,0.55, body extent -0.85,-0.55 0.85,0.55, height 0.61
ESD_QFN-6L_1P7X1P5_P050 [mm]
  rect 0.25x0.6 smd mask+0.05: 1(-0.5,-0.65) 2(0,-0.65) 3(0.5,-0.65) 4(0.5,0.65) 5(0,0.65) 6(-0.5,0.65)
  silkscreen extent -0.9,-0.8 0.9,0.8, body extent -0.9,-0.8 0.9,0.8, height 0.56
"Header F 1x6x2.54 TH V" [mm] "1x6x2.54 Header TH V Female"
  rect 1.8x1.8 hole 1: 1(0,0)
  round 1.8 hole 1: 2(2.54,0) 3(5.08,0) 4(7.62,0) 5(10.16,0) 6(12.7,0)
  silkscreen extent -1.4,-1.4 14.1,1.4, body extent -1.42,-1.28 14.07,1.22, height 8.5
"Header F 1x8x2.54 TH V" [mm] "1x8x2.54 Header TH V Female"
  rect 1.8x1.8 hole 1: 1(0,0)
  round 1.8 hole 1: 2(2.54,0) 3(5.08,0) 4(7.62,0) 5(10.16,0) 6(12.7,0) 7(15.24,0) 8(17.78,0)
  silkscreen extent -1.4,-1.4 19.18,1.4, body extent -1.42,-1.35 19.15,1.15, height 8.5
"Header F 1x10x2.54 TH V" [mm] "1x10x2.54 Header TH V Female"
  rect 1.8x1.8 hole 1: 1(0,0)
  round 1.8 hole 1: 2(2.54,0) 3(5.08,0) 4(7.62,0) 5(10.16,0) 6(12.7,0) 7(15.24,0) 8(17.78,0) 9(20.32,0) 10(22.86,0)
  silkscreen extent -1.4,-1.4 24.26,1.4, body extent -1.42,-1.33 24.23,1.17, height 8.5
"Header M 1x2x2.54 TH V" [mm] "1x2x2.54 Header TH V Male"
  rect 1.8x1.8 hole 1: 1(0,0)
  round 1.8 hole 1: 2(2.54,0)
  silkscreen extent -1.4,-1.4 3.94,1.4, body extent -1.27,-1.27 3.81,1.27, height 8.55
"Header M 2x4x2.54 TH V" [mm] "2x4x2.54 Header TH V Male"
  rect 1.8x1.8 hole 1: 1(0,0)
  round 1.8 hole 1: 2(0,2.54) 3(2.54,0) 4(2.54,2.54) 5(5.08,0) 6(5.08,2.54) 7(7.62,0) 8(7.62,2.54)
  silkscreen extent -1.47,-1.43 9.02,3.97, body extent -1.3,-1.3 8.86,3.78, height 8.5
"Header M 2x8x2.54 TH V" [mm] "2x8x2.54 Header TH V Male"
  rect 1.8x1.8 hole 1: 1(0,0)
  round 1.8 hole 1: 2(0,2.54) 3(2.54,0) 4(2.54,2.54) 5(5.08,0) 6(5.08,2.54) 7(7.62,0) 8(7.62,2.54) 9(10.16,0) 10(10.16,2.54) 11(12.7,0) 12(12.7,2.54) 13(15.24,0) 14(15.24,2.54) 15(17.78,0) 16(17.78,2.54)
  silkscreen extent -1.47,-1.43 19.15,3.97, body extent -1.32,-1.27 19,3.81, height 8.5
"Header M 2x19x2.54 TH M_top + M_bottom" [mm] "2x19x2.54 Header TH V MaleTop + MaleBottom (Morphos_Nucleo64)"
  rect 1.8x1.8 hole 1: 1(0,0)
  round 1.8 hole 1: 2(0,2.54) 3(2.54,0) 4(2.54,2.54) 5(5.08,0) 6(5.08,2.54) 7(7.62,0) 8(7.62,2.54) 9(10.16,0) 10(10.16,2.54) 11(12.7,0) 12(12.7,2.54) 13(15.24,0) 14(15.24,2.54) 15(17.78,0) 16(17.78,2.54) 17(20.32,0) 18(20.32,2.54) 19(22.86,0) 20(22.86,2.54) 21(25.4,0.127) 22(25.4,2.667) 23(27.94,0.127) 24(27.94,2.667) 25(30.48,0.127) 26(30.48,2.667) 27(33.02,0.127) 28(33.02,2.667) 29(35.56,0.127) 30(35.56,2.667) 31(38.1,0) 32(38.1,2.54) 33(40.64,0) 34(40.64,2.54) 35(43.18,0) 36(43.18,2.54) 37(45.72,0) 38(45.72,2.54)
  silkscreen extent -1.47,-1.43 47.24,3.97, body extent -1.32,-1.24 46.94,3.84, height 8.38
"Header NF 1x2x2.54 TH" [mm] "1x2x2.54 Header TH Not Fitted"
  rect 1.8x1.8 hole 1: 1(0,0)
  round 1.8 hole 1: 2(2.54,0)
  silkscreen extent -1.4,-1.4 3.94,1.4
"Header NF 1x5x2.54 TH" [mm] "1x5x2.54 Header TH Not Fitted"
  rect 1.8x1.8 hole 1: 1(0,0)
  round 1.8 hole 1: 2(2.54,0) 3(5.08,0) 4(7.62,0) 5(10.16,0)
  silkscreen extent -1.4,-1.4 11.56,1.4
"Header NF 1x6x2.54 TH" [mm] "1x6x2.54 Header TH Not Fitted"
  rect 1.8x1.8 hole 1: 1(0,0)
  round 1.8 hole 1: 2(2.54,0) 3(5.08,0) 4(7.62,0) 5(10.16,0) 6(12.7,0)
  silkscreen extent -1.4,-1.4 14.1,1.4
HSMF-A201 [mm] "LED"
  rect 1.5x1.1 smd: 1(-1.5,0.75) 2(1.5,0.75) 3(1.5,-0.75) 4(-1.5,-0.75)
  silkscreen extent -2.3,-1.55 1.75,1.93, body extent -1.6,-1.4 1.6,1.4, height 1.3
IND_0402_MURATA_LQW15AN_H0P5 [mm] "MCD-01606"
  rect 0.65x0.9 smd mask+0.05: 1(-0.475,0) 2(0.475,0)
  silkscreen extent -0.05,-0.35 0.05,0.35, body extent -0.55,-0.35 0.55,0.35, height 0.6
"Jumper 2.54mm BLACK" [mm] "Jumper 2.54mm Black"
  body extent -2.5,-1.2 2.5,1.2, height 8.5
"LOGO CE" [mm]
  silkscreen extent -3.27,-3.31 4.33,3.3
"LOGO ESD" [mm]
  silkscreen extent -3.23,-2.59 3.66,3.68
LOGO_Nucleo_www [mm] "Web Link for STM32 Nucleo Board"
LOGO_ST_Size3 [mm]
  silkscreen extent -4.5,-2.36 4.7,2.57
LOGO_StickerArea_Border [mm] "Sticker Area reservation 22x6 mm Border only"
  silkscreen extent 0,0 22,6
LOGO_STM32 [mm]
  silkscreen extent -3.9,-4.23 4.33,3.95
LQFP48_7X7_P050 [mm]
  rect 0.3x1.2 smd mask+0.05: 1(-2.75,-4.25) 2(-2.25,-4.25) 3(-1.75,-4.25) 4(-1.25,-4.25) 5(-0.75,-4.25) 6(-0.25,-4.25) 7(0.25,-4.25) 8(0.75,-4.25) 9(1.25,-4.25) 10(1.75,-4.25) 11(2.25,-4.25) 12(2.75,-4.25) 25(2.75,4.25) 26(2.25,4.25) 27(1.75,4.25) 28(1.25,4.25) 29(0.75,4.25) 30(0.25,4.25) 31(-0.25,4.25) 32(-0.75,4.25) 33(-1.25,4.25) 34(-1.75,4.25) 35(-2.25,4.25) 36(-2.75,4.25)
  rect 1.2x0.3 smd mask+0.05: 13(4.25,-2.75) 14(4.25,-2.25) 15(4.25,-1.75) 16(4.25,-1.25) 17(4.25,-0.75) 18(4.25,-0.25) 19(4.25,0.25) 20(4.25,0.75) 21(4.25,1.25) 22(4.25,1.75) 23(4.25,2.25) 24(4.25,2.75) 37(-4.25,2.75) 38(-4.25,2.25) 39(-4.25,1.75) 40(-4.25,1.25) 41(-4.25,0.75) 42(-4.25,0.25) 43(-4.25,-0.25) 44(-4.25,-0.75) 45(-4.25,-1.25) 46(-4.25,-1.75) 47(-4.25,-2.25) 48(-4.25,-2.75)
  silkscreen extent -4.52,-4.53 3.52,3.52, body extent -4.5,-4.5 4.5,4.5, height 1.6
MOS_SOT23-5L [mm]
  rect 0.6x1.3 smd mask+0.05: 1(-0.95,-1.1) 2(0,-1.1) 3(0.95,-1.1) 4(0.95,1.1) 5(-0.95,1.1)
  silkscreen extent -1.6,-0.95 1.6,0.97, body extent -1.52,-1.25 1.52,1.25, height 1.45
NX2012_2P [mm]
  rect 1x1.25 smd: 1(0,0) 2(1.5,0)
  silkscreen extent 0.63,-0.76 0.89,0.76, body extent -0.33,-0.76 1.88,0.76, height 0.75
NX2016_4P [mm]
  rect 0.85x0.75 smd: 1(-0.675,-0.525) 2(0.675,-0.525) 3(0.675,0.525) 4(-0.675,0.525)
  silkscreen extent -1.07,-1.16 1.02,0.81, body extent -1,-0.8 1,0.8, height 0.7
SB-tiny [mil]
  round 10 smd paste-10 mask+0.04: 1(-19.69,0)
  round 10 smd paste-10.08 mask+0.04: 2(20,0)
  L1 region: -5.91,19.69 13.78,0 -5.91,-19.68 25,-19.68 25,19.69
  L1 region: -30,-19.68 -30,19.69 -15.75,19.69 3.94,0 -15.75,-19.68
  silkscreen extent -32,-23 27,23
"Shield 17.2x17.2x3" [mm] "Metallic Shield 17.2x17.2mm height =3mm tickness=0.2mm"
  silkscreen extent 17.81,28.6 35.08,45.75, body extent 17.84,28.6 35.04,45.8, height 3
"Shield Clip_A 3.9x1.1x1.28" [mm] "Shield Clip 3.9x1.1x1.28 - Harwin S0951-46R - Full pad"
  rect 0.48x0.5 smd mask+0.075: 1(-1.81,0) 1(1.81,0)
  rect 0.7x0.5 smd mask+0.075: 1(-1.1,0) 1(1.1,0)
  rect 1.1x1.2 smd mask+0.075: 1(0,0)
  body extent -1.95,-0.55 1.95,0.55, height 1.28
SMA_T_9.52_NF [mm]
  rect 2.5x0.6 smd mask+0.05: 1(-2.413,0)
  rect 4.9x1.2 smd: 2(-3.556,-4.25) 2(-3.556,4.25)
  rect 4.9x1.2 smd far side: 2(-3.556,-4.25) 2(-3.556,4.25)
SOD523 [mm]
  rect 0.65x0.3 smd mask+0.05: A(-0.675,0) K(0.675,0)
  silkscreen extent -0.81,-0.41 0.91,0.41, body extent -0.81,-0.41 0.81,0.41, height 0.62
SOD-323 [mm] "Diode"
  rect 1.35x0.4 smd: 1(-1.2,0) 2(1.2,0)
  silkscreen extent -1.4,-0.75 1.94,0.75, body extent -1.35,-0.72 1.35,0.72, height 1.17
SOT23-3 [mm]
  rect 0.9x0.95 smd: 1(-0.95,-2.35) 2(0.95,-2.35) 3(0,0)
  silkscreen extent -1.9,-3.35 1.3,0, body extent -1.46,-2.42 1.46,0.06, height 1.1
SOT23-5 [mil]
  rect 50x20 smd: 1(-50,37.5) 2(-50,0.5) 3(-50,-37.5) 4(50,-37.5) 5(50,37.5)
  silkscreen extent -104,-8 55,77, body extent -55,-57 55,57, height 57
SOT223_SC73_A [mm]
  rect 1.5x1.65 smd mask+0.05: 1(-2.3,-3.175) 2(0,-3.175) 3(2.3,-3.175)
  rect 3.5x1.65 smd mask+0.05: 2(0,3.175)
  silkscreen extent -3.35,-2.15 3.35,2.12, body extent -3.35,-3.48 3.35,3.48, height 1.8
SOT353-1 [mm] "SOT353-1 5 pins package"
  rect 0.8x0.37 smd mask+0.075: 1(-0.076,0) 2(-0.076,-0.65) 3(-0.076,-1.3) 4(1.951,-1.3) 5(1.951,0)
  silkscreen extent -0.38,-1.7 1.91,0.51, body extent -0.31,-1.73 2.09,0.47, height 1.1
ST_CSP650x58P2x3_160x100x42 [mm] "ST_CSP650X58P2X3_160X100X42"
  rect 0.3x0.3 smd paste-0.05 mask-0.05: A1(-0.25,0.587) A2(-0.25,0) A3(-0.25,-0.587) B1(0.25,0.587) B2(0.25,0) B3(0.25,-0.587)
  silkscreen extent -0.74,-0.86 0.56,1.03, body extent -0.5,-0.8 0.5,0.8, height 0.45
Sticker_BrdRef_21x5mm [mm] "Sticker_BrdRef_21x5mm White"
  silkscreen extent 0,0 21,5, body extent 0,0 21,5, height 0.1
"Sticker_CPN_FG 16x5mm" [mm] "Sticker_CPN_FG 16x6mm White"
  silkscreen extent 0,0 16,5, body extent 0,0 16,5, height 0.1
"Sticker_FCC_ID 16x5mm" [mm] "Sticker_FCC_ID 16x5mm White"
  silkscreen extent 0,0 16,5, body extent 0,0 16,5, height 3.1
"SW-PB SMD KMR2" [mm]
  rect 0.9x1 smd: 1(-2.05,0.8) 1(2.05,0.8) 2(-2.05,-0.8) 2(2.05,-0.8)
  silkscreen extent -2.4,-1.52 2.42,1.53, body extent -2.41,-1.52 2.41,1.52, height 2.52
SWI_SPDT-RA_TE-CONNECTIVITY_MLL1200S_1P2T [mm] "MCD-02081"
  rect 1x0.8 smd mask+0.05: 0(-3.75,-1.15) 0(-3.75,1.15) 0(3.75,-1.15) 0(3.75,1.15)
  rect 0.7x1.1 smd mask+0.05: 1(-2.25,2.05) 2(0.75,2.05) 3(2.25,2.05)
  round 0 hole 0.9 unplated mask+0.05: NPTH1(-1.5,0) NPTH2(1.5,0)
  silkscreen extent -3.5,-2.9 3.5,1.4, body extent -3.85,-2.9 3.85,2.24, height 1.75
TSSOP20 [mm]
  rect 1.55x0.25 smd: 1(0,0)
  oval 1.55x0.25 smd: 2(0,-0.65) 3(0,-1.3) 4(0,-1.95) 5(0,-2.6) 6(0,-3.25) 7(0,-3.9) 8(0,-4.55) 9(0,-5.2) 10(0,-5.85) 11(5.6,-5.85) 12(5.6,-5.2) 13(5.6,-4.55) 14(5.6,-3.9) 15(5.6,-3.25) 16(5.6,-2.6) 17(5.6,-1.95) 18(5.6,-1.3) 19(5.6,-0.65) 20(5.6,0)
  silkscreen extent -0.77,-6.27 5.64,0.61, body extent -0.43,-6.17 5.97,0.33, height 1.2
USBMICROB_MOLEX_105017-0001_H2P90 [mm]
  rect 0.4x1.35 smd mask+0.05: 1(-1.3,4.15) 2(-0.65,4.15) 3(0,4.15) 4(0.65,4.15) 5(1.3,4.15)
  oval 1.2x1.9 hole 0.6 slot 1.3 at 90 deg mask+0.05: 6(-3.5,1.45) 6(3.5,1.45)
  round 1.5 hole 0.9 mask+0.05: 6(-2.5,4.15) 6(2.5,4.15)
  rect 1.5x1.9 smd mask+0.05: 6(-1,1.45) 6(1,1.45)
  L1 region: -3.5,2.4 -2.3,2.4 -2.3,0.5 -3.5,0.5
  L1 region: 2.3,2.4 3.5,2.4 3.5,0.5 2.3,0.5
  silkscreen extent -4.45,0 4.45,5.3, body extent -4.1,-1.15 4.1,4.66, height 2.9
VFQFPN68_8x8x0.1_p0.4 [mm]
  oct 1x0.25 smd mask+0.04: 1(-3.878,3.2) 2(-3.878,2.8) 3(-3.878,2.4) 4(-3.878,2) 5(-3.878,1.6) 6(-3.878,1.2) 7(-3.878,0.8) 8(-3.878,0.4) 9(-3.878,0) 10(-3.878,-0.4) 11(-3.878,-0.8) 12(-3.878,-1.2) 13(-3.878,-1.6) 14(-3.878,-2) 15(-3.878,-2.4) 16(-3.878,-2.8) 17(-3.878,-3.2) 35(3.903,-3.2) 36(3.903,-2.8) 37(3.903,-2.4) 38(3.903,-2) 39(3.903,-1.6) 40(3.903,-1.2) 41(3.903,-0.8) 42(3.903,-0.4) 43(3.903,0) 44(3.903,0.4) 45(3.903,0.8) 46(3.903,1.2) 47(3.903,1.6) 48(3.903,2) 49(3.903,2.4) 50(3.903,2.8) 51(3.903,3.2)
  oct 0.25x1 smd mask+0.04: 18(-3.2,-3.903) 19(-2.8,-3.903) 20(-2.4,-3.903) 21(-2,-3.903) 22(-1.6,-3.903) 23(-1.2,-3.903) 24(-0.8,-3.903) 25(-0.4,-3.903) 26(0,-3.903) 27(0.4,-3.903) 28(0.8,-3.903) 29(1.2,-3.903) 30(1.6,-3.903) 31(2,-3.903) 32(2.4,-3.903) 33(2.8,-3.903) 34(3.2,-3.903) 52(3.2,3.903) 53(2.8,3.903) 54(2.4,3.903) 55(2,3.903) 56(1.6,3.903) 57(1.2,3.903) 58(0.8,3.903) 59(0.4,3.903) 60(0,3.903) 61(-0.4,3.903) 62(-0.8,3.903) 63(-1.2,3.903) 64(-1.6,3.903) 65(-2,3.903) 66(-2.4,3.903) 67(-2.8,3.903) 68(-3.2,3.903)
  rect 6.5x6.5 smd paste-5 mask-0.01: 69(0,0)
  silkscreen extent -5.14,-4 4,5.07, body extent -4.01,-3.99 3.99,3.99, height 1.2

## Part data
C1 C2: library part MCD-00205, "Capacitor, MLCC, 100pF, 50V, NPO, 5%, 0402, T=0,5mm", Manufacturer=YAGEO, Manufacturer_Part_Number=CC0402JRNPO9BN101, Package=C0402
C3 C6 C7 C8 C12 C13 C14 C15 C16 C17 C18 C19 C20 C21 C22 C23 C24 C25 C26 C27 C28 C29 C31 C32 C33 C34 C36 C37 C39 C40 C41 C42 C43 C44 C45 C46 C47 C48 C49 C50: library part CAP_NPOL, "Capacitor_not polarized"
C9 C10 C11: library part CAP_POL, "Condensateur_polarise"
CN1 CN15: "USB-MICRO-B, 1050170001, SMT, MOLEX", Manuf_1=MOLEX
CN6 CN9: library part HEADER_1X8
CN7 CN10: library part HEADER_2X19
D1: library part BAT54K, "Schottky Diode"
D2: library part Diode, "Default Diode"
JP2 JP3 JP4 JP6: library part HEADER_1X2_L
L1: library part IND_74479777310A, "Coil Wurtz 10uH ref: 74479777310A"
L2: library part IND_FCM1608KF-601T03
L3 L4: library part INDUCTOR_SMD_STDL
L5: library part MCD-02063, "inductor, 10nH +-2%, 100mA max,1.3 ohm DC max, Q min = 13,0402", Alternate_Manufacturer=N/A, Manufacturer=MURATA, Manufacturer_Part_Number=LQP15MN10NG02, Package=L0402
LED1: library part LED, "Light-Emitting Diode", Color=BLUE
LED2 LED3 LED4 LED5: library part LED, "Light-Emitting Diode"
LED6: library part LD_BICOLOR_CMS, "Bicolor Led", Manuf_1="Avago Technologies", Manuf_2=kingbright, Manuf_Part_1=HSMF-A201-A00J1, Manuf_Part_2=KAA-3528SURKCGKC
Q1: "2N2222_SOT23"
R1 R2 R3 R4 R5 R6 R7 R8 R9 R10 R11 R12 R13 R14 R15 R16 R17 R18 R19 R20 R21 R22 R23 R24 R25 R26 R27 R28 R29 R30 R31 R32 R33: library part RES, "Resistor"
SB1 SB2 SB3 SB4 SB5 SB6 SB7 SB8 SB9 SB10 SB11 SB12 SB13 SB14 SB15 SB16 SB17 SB18 SB22 SB23 SB24 SB25 SB26 SB27 SB28 SB30 SB31 SB32 SB33 SB34 SB35 SB36 SB37 SB38 SB39 SB40 SB41 SB42 SB45 SB46 SB47 SB48 SB49 SB50 SB51: library part Strap2, "Solder Jumper"
SC1 SC2 SC3 SC4: "Harwin S0951-46R"
SH1: library part Shield, "Shield"
STICKER_1: library part LOGO_Sticker_FCC_ID, "Sticker for FCC_ID 16x5mm"
STICKER_2: library part LOGO_Sticker_BrdRef, "Sticker_BrdRef 21x5mm"
STICKER_3: library part LOGO_Sticker_CPN_FG, "Sticker for CPN_FG 16x5mm"
SW1 SW2 SW3 SW4: library part SW-PB_1, "Push-button SMD"
SW5: library part MCD-02081, "SPDT RA SMT SLIDE SWITCH", Manufacturer=TE_Connectivity, Manufacturer_Part_Number=MLL1200S
U2: "IC REG LDO 5V 0.8A SOT223", Manuf_1=STM
U3: "3.3V voltage regulator 500mA"
U4: library part MCD-01785, "5V Power Switch, 0.85A, RDSon 130mOhm max, with active low enable pin", Manufacturer="TEXAS INSTRUMENTS", Manufacturer_Part_Number=TPS2041CDBVT, Package=SOT23_5p
U5: "3.3V low drop voltage regulator", Manufacturer=STMicroelectronics, Temperature Max=+125°C, Temperature Min=-40°C
U6 U9: library part MCD-00649, "Common mode filter with ESD protection for USB 2.0 interface", Manufacturer=STMICROELECTRONICS
U7: "TXS0108E Bi-directional Level Shifter TSSOP20"
U8: "Medium-density performance line ARM-based 32-bit MCU with 128KB Flash", Manuf_1=STM
U11 U13: library part MCD-00251, "High power transient voltage suppressor, 7V breakdown", Manufacturer=STMICROELECTRONICS, Manufacturer_Part_Number=ESDA7P60-1U1M
U12: library part MCD-02059, "2.4 GHz low pass filter matched to STM32WBx5Cx/Rx", Manufacturer=STMICROELECTRONICS, Package="Bumpless CSP"
X1: "Crystal NDK 2.0x1.6mm  32 MHz", Manufacturer=NDK, Manufacturer P/N="NX2016SA 32 MHz EXS00A-CS06654"
X2: "Crystal NDK 2.0x1.2mm  32.768 KHz", Manufacturer=NDK, Manufacturer P/N="NX2012SA 32.768KHz  EXS00A-MU00389"
X3: library part MCD-00092, "Crystal 8MHz, 8pF, +-20ppm, 500ohms max,  SMD", Manufacturer=NDK, Manufacturer_Part_Number="NX3225GD 8MHz EXS00A-CG04874"

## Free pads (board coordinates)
  round 0.3 on Drill Drawing: 19(50.454,13.279)
  round 0.3 hole 0.2: 65(53.56,30.734) 105(54.205,44.276) 106(54.225,43.816)

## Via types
v1: diameter 0.3, hole 0.2, L1 to L4, tented both sides, 662 vias
v2: diameter 0.403, hole 0.2, L1 to L4, tented both sides, 628 vias
v3: diameter 0.4, hole 0.25, L1 to L4, tented both sides, 50 vias
v4: diameter 0.5, hole 0.3, L1 to L4, tented both sides, 24 vias

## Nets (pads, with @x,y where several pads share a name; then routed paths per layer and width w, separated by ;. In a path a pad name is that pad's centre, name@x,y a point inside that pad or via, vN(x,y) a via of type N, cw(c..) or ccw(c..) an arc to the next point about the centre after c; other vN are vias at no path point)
3V3: C13.1 C16.1 CN6.2 CN6.4 CN7.12 CN7.16 pad.105 pad.106 SB26.2 SB33.2 U3.4 | length 75.4
  L1 w1: 54.718,43.816 54.718,44.222 54.755,44.259 55.619,44.259 C13.1@56.46,45.1 56.46,47.616 55.967,48.109 55.224,48.109
  L3 w0.8: CN6.2@10.87,38.06 11.615,38.06 13.894,35.781 27.12,35.781 27.122,35.783 27.66,35.783 27.662,35.781 32.321,35.781 v1@33.055,36.515
  L3 w1.5: CN7.16@5.79,32.98 8.287,32.98 ; CN7.12@5.79,38.06 8.242,38.06 ; CN6.4@10.87,32.98 8.287,32.98 ; CN6.2@10.87,38.06 8.242,38.06 ; 8.242,38.06 8.287,38.015 8.287,32.98
  L4 w0.2: v1(16.475,36.002) 16.475,36.427 17.927,37.879 SB33.2@17.927,38.505
  L4 w0.8: v1@33.066,36.536 34.056,37.525 34.757,37.525 34.743,37.539 34.743,38.132 35.503,38.893 47.482,38.893 47.836,39.246 47.836,40.786 49.094,42.044 53.682,42.044 54.732,43.094 v1(54.732,43.547) 54.732,44.094 54.718,44.108 54.385,44.108 54.313,44.036
  other v1: 32.988,36.536
3V3_STLINK: C22.1 C27.1 C41.1 C43.1 C47.1 C48.1 C49.1 C50.1 LED6.4 Q1.3 R24.2 R30.1 R31.2 R32.2 SB37.1 U5.5 U7.19 U8.1 U8.9 U8.24 U8.36 U8.48 U10.5 | length 136.7
  L1 w0.127: U7.19@36.475,23.781 C41.1@37.996,23.781 ; C41.1@38.011,23.766 v1@39.375,23.766 ; 41.788,15.096 U8.24@42.96,15.096 ; U8.9@45.96,22.096 45.96,23.116 45.26,23.816 C47.1@45.26,24.857 45.26,25.256 45.49,25.486 46.09,25.486 46.24,25.636 R24.2@46.24,26.065 ; U8.1@49.96,22.096 49.96,22.742 50.07,22.853 52.454,22.853 52.81,22.496 52.81,20.647 C50.1@52.821,20.636 ; U8.48@51.46,20.596 52.781,20.596 C50.1@52.821,20.636 ; v4@53.716,21.644 53.716,21.197 53.32,20.801 52.986,20.801 C50.1@52.821,20.636
  L1 w0.25: U8.36@49.96,13.596 49.96,12.905 50.079,12.786 50.454,12.786
  L1 w0.3: U10.5@39.319,18.186 40.022,18.186 v4(40.028,18.192) ; C48.1@40.909,15.076 41.768,15.076 ; v4@41.842,16.111 41.842,15.15 41.788,15.096 41.768,15.076 ; U8.24@42.96,15.096 42.94,15.076 41.768,15.076 ; R24.2@46.24,26.065 46.279,26.104 v1(46.279,26.603) ; LED6.4@47.42,3.014 47.896,3.014 48.354,3.472 v1(48.354,9.252) ; v4(49.789,8.67) 50.391,8.67 Q1.3@50.432,8.629 ; v4@50.442,13.267 50.452,12.877 50.454,12.786 v4(50.454,13.279) v4@50.442,13.267
  L1 w0.4: v1(61.658,50.087) 61.658,27.969 62.465,27.162 v1@62.465,21.604
  L3 w0.3: v4@40.04,18.164 40.04,16.116 v4(40.056,16.1) ; v4@40.142,20.463 v4@40.142,20.469 ; v4@50.45,13.275 v4@50.45,13.294
  L3 w0.5: v1(36.942,13.207) 36.942,15.466 37.576,16.1 v4(40.056,16.1) 41.831,16.1 v4@41.842,16.111 ; v1(39.375,23.764) 39.375,21.423 40.142,20.656 v4@40.142,20.469 ; v4@40.04,16.116 40.028,16.128 v4(40.028,18.192) 40.028,19.955 40.142,20.069 40.142,20.463 v4@40.139,20.466 ; v4(49.789,8.67) 48.936,8.67 v1(48.354,9.252) 48.354,11.455 48.773,11.874 49.92,11.874 50.45,12.404 50.45,13.275 v4(50.454,13.279)
  L4 w0.3: C27.1@36.913,12.706 C27.1@36.92,12.713 36.942,12.735 v1(36.942,13.207) ; v4@41.83,16.094 45.36,16.094 46.2,16.934 48.22,16.934 ; v1(46.279,26.603) 46.281,26.601 46.281,25.233 48.22,23.294 48.22,21.624 ; v4@50.45,13.294 50.45,15.921 49.437,16.934 48.22,16.934 ; SB37.1@56.511,14.739 57.275,14.739 57.598,15.062 57.598,18.383 57.176,18.805 56.39,18.805 55.73,19.465 55.73,21.463 55.73,21.644 48.24,21.644 48.22,21.624 ; 48.22,16.934 48.22,21.624
  L4 w0.4: 55.73,21.463 55.837,21.57 v1@62.465,21.57 ; R31.2@60.925,52.233 60.925,50.82 v1(61.658,50.087)
  L4 w0.5: U5.5@35.02,13.731 35.71,13.041 C22.1@35.71,12.706 C27.1@36.913,12.706
  other v1: 62.477,21.592
  other v4: 41.845,16.097 40.05,17.173 40.272,20.524 53.722,21.655
5V: C14.1 C15.1 CN6.5 CN7.18 D2.1 JP1.2 JP1.4 JP1.6 JP1.8 R10.1 SB28.2 U3.1 U3.6 | length 106.6
  L1 w0.2: v1@52.237,45.257 52.237,47.87 52.476,48.109 U3.6@53.01,48.109 ; v1@52.286,45.249 U3.1@53.056,45.249 ; R10.1@53.97,7.073 53.97,7.212 54.623,7.865 54.623,10.039 56.678,12.094 v1(56.678,19.918)
  L1 w1: JP1.8@49.865,47.505 51.266,48.906 53.01,48.906 ; U3.6@53.01,48.109 53.01,48.906 ; 53.526,48.906 53.01,48.906
  L3 w0.2: v1(52.246,45.257) 52.246,42.498 54.744,40 54.744,22.6 56.678,20.666 v1(56.678,19.918)
  L3 w0.8: CN6.5@10.87,30.44 11.394,30.44 15.403,34.449 18.074,34.449 18.077,34.446 35.831,34.446 40.508,39.124 40.508,47.056 40.957,47.505 JP1.2@42.245,47.505
  L3 w1.5: CN7.18@5.79,30.44 CN6.5@10.87,30.44
  L4 w0.2: v1(56.678,19.918) 56.662,19.934 D2.1@56.87,19.934 56.87,19.894 D2.1@56.86,19.884
  L4 w0.3: SB28.2@36.127,34.908 v1(36.254,34.908)
  L4 w1: JP1.2@42.245,47.505 JP1.4@44.785,47.505 JP1.6@47.325,47.505 JP1.8@49.865,47.505
5V_EXT: CN7.6 JP1.1 | length 48.3
  L3 w0.4: 8.98,39.314 11.799,39.314
  L3 w0.5: CN7.6@6.014,45.68 CN7.6@5.79,45.68 7.09,44.38 7.09,42.602 7.089,42.601 7.089,41.205 8.98,39.314 ; 11.799,39.314 14.093,37.02 32.306,37.02 32.748,37.462 36.844,37.462 39.575,40.193 v1(39.575,44.961) ; JP1.1@42.245,44.905 JP1.1@42.245,44.965
  L4 w0.5: v1(39.575,44.961) 42.241,44.961 JP1.1@42.245,44.965
5V_INT: C9.1 JP1.3 R33.2 U2.2 | length 18.6
  L1 w0.5: R33.2@37.593,37.594 38.115,37.594 U2.2@39.125,36.584
  L1 w1: U2.2@39.125,36.584 U2.2@45.475,36.584 45.475,39.153 C9.1@42.901,41.728 ; C9.1@42.857,41.684 C9.1@42.901,41.728 ; JP1.3@44.785,44.965 44.785,43.612 C9.1@42.901,41.728
5V_USB_MCU: C1.2 CN1.1 CN10.8 JP1.5 U11.1 | length 66.4
  L2 w0.5: JP1.5@47.325,44.965 48.76,43.53 52.49,43.53 54.874,45.914 61.432,45.914 62.932,44.414 65.476,44.414 CN10.8@66.75,43.14
  L3 w0.5: v4(43.478,6.071) 43.515,6.108 43.515,7.452 44.68,8.617 44.68,30.984 44.99,31.294 44.99,42.63 JP1.5@47.325,44.965 ; CN10.8@66.75,43.074 CN10.8@66.75,43.14
  L4 w0.5: CN1.1@41.659,4.135 41.659,4.963 42.766,6.07 C1.2@44.054,6.07
5V_USB_STLINK: C2.1 C11.1 C21.1 C25.1 CN15.1 pad.65 R11.1 R12.1 R16.2 SB25.2 U4.5 U5.1 U5.3 U13.1 | length 78.8
  L1 w0.3: R12.1@52.34,7.234 52.34,9.001 52.714,9.375 v4(53.389,9.375)
  L1 w0.5: 52.035,37.914 52.335,37.614 52.335,36.358 U4.5@52.523,36.17 ; v4(53.389,9.375) 53.389,10.424 54.433,11.469 R16.2@54.433,12.886 ; pad.65@53.604,30.754 53.175,30.754 C11.1@52.645,31.284 52.645,32.657 52.105,33.197 51.72,33.197 51.335,33.582 51.335,35.806 51.699,36.17 U4.5@52.523,36.17 ; R11.1@54.034,35.62 54.034,35.867 53.731,36.17 U4.5@52.523,36.17
  L3 w0.5: v4(53.389,9.375) 54.539,9.375 54.541,9.373 55.53,10.362 55.57,10.402 55.57,20.666 53.56,22.676 pad.65@53.56,30.734
  L4 w0.2: U5.1@32.48,13.731 33.188,13.731 33.511,14.055 33.511,15.323 33.198,15.636 U5.3@32.48,15.636
  L4 w0.5: U5.1@32.48,13.731 32.48,13.005 C25.1@32.891,12.594 32.478,12.181 C21.1@32.478,11.274 32.478,10.364 33.118,9.724 39.252,9.724 ; 39.259,9.724 47.52,9.724 47.97,10.174 47.97,11.614 48.855,12.499 53.318,12.499 53.529,12.288 54.421,12.288 v4@54.429,12.296 ; v4(53.389,9.375) 53.389,8.997 U13.1@54.22,8.166 ; CN15.1@54.207,6.15 54.207,8.153 U13.1@54.22,8.166 ; C2.1@55.412,8.019 55.398,8.005 54.38,8.005 U13.1@54.22,8.166
  other v4: 54.421,12.306
AIN_1: R26.1 R28.1 U8.10 | length 4.2
  L1 w0.127: R26.1@43.28,24.867 R28.1@44.25,24.867 ; R28.1@44.26,24.857 44.26,23.986 45.46,22.786 U8.10@45.46,22.096
ANT: C37.2 L3.2 | length 1.4
  L1 w0.6: 19.579,56.514 19.579,56.793 ; C37.2@19.646,56.307 19.646,56.177 L3.2@20.598,56.177
AT2: CN3.3 SB22.2 | length 5.7
  L4 w0.15: CN3.3@9.146,49.587 10.596,49.587 11.277,48.906 14.312,48.906 14.312,49.137
AT3: CN3.4 SB23.2 | length 4.6
  L4 w0.1: CN3.4@9.6,52.157 CN3.4@9.613,52.144
  L4 w0.2: CN3.4@9.146,52.127 10.372,53.353 10.372,54.334 11.325,55.287 SB23.2@11.813,55.287
AVDD: CN5.8 CN10.7 SB49.2 SB50.2 SB51.2 | length 40.1
  L3 w1: CN5.8@59.13,44.664 CN5.8@59.13,44.789
  L4 w1: 33.995,34.408 33.995,31.891 37.966,31.891 42.22,36.145 48.033,36.145 49.323,37.435 49.323,39.739 50.37,40.786 54.161,40.786 58.039,44.664 CN5.8@59.13,44.664 61.05,44.664 62.574,43.14 CN10.7@64.21,43.14
BOOT0: CN7.7 R6.1 U1.5 | length 33.5
  L1 w0.2: U1.5@28.722,42.652 28.725,42.655 v1(29.346,42.655)
  L2 w0.2: v1(16.303,41.911) 16.303,42.537 17.409,43.643 23.44,43.643 24.431,42.652 24.434,42.655 v1(29.346,42.655)
  L3 w0.2: v1(12.979,43.159) 14.227,41.911 v1(16.303,41.911)
  L4 w0.2: CN7.7@3.25,43.14 4.499,44.389 6.894,44.389 8.01,43.273 12.865,43.273 v1(12.979,43.159) ; v1(29.346,42.655) 29.53,42.655 29.833,42.352 29.833,41.164 29.565,40.896 29.565,40.035 29.905,39.695 R6.1@30.107,39.695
